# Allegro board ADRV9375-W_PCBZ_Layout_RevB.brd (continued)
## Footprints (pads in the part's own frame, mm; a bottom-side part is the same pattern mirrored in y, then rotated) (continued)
CNSAMTECTSW-108-08-G-D-ST
  rect 1.651x1.651 hole 1.143: 1(0,0)
  round 1.651 hole 1.143: 2(0,2.54) 3(2.54,0) 4(2.54,2.54) 5(5.08,0) 6(5.08,2.54) 7(7.62,0) 8(7.62,2.54) 9(10.16,0) 10(10.16,2.54) 11(12.7,0) 12(12.7,2.54) 13(15.24,0) 14(15.24,2.54) 15(17.78,0) 16(17.78,2.54)
CNWIELAND3225
  rect 2.159x2.159 hole 1.651: 1(0,0)
  round 2.159 hole 1.651: 2(5,0)
DO214AA3
  rect 1.778x2.159 smd: A(2.032,0) C(-2.032,0)
ETC1
  rect 0.762x1.397 smd: 1(-1.27,1.714) 2(0,1.714) 3(1.27,1.714) 4(1.27,-1.714) 5(-1.27,-1.714)
F1206
  rect 1.143x2.032 smd: 1(-1.333,0) 2(1.333,0)
L0201H13
  rect 0.254x0.305 smd: 1(-0.277,0) 2(0.277,0)
L0402
  rect 0.889x0.813 smd: 1(-0.635,0) 2(0.635,0)
L0603
  rect 0.583x0.813 smd: 1(-0.737,0)
  rect 0.889x0.813 smd: 2(0.737,0)
L0805
  rect 1.143x1.27 smd: 1(-0.953,0) 2(0.953,0)
LCC4H210
  rect 1.27x2.286 smd: 1(-2.54,-3.556) 2(2.54,-3.556) 3(2.54,3.556) 4(-2.54,3.556)
LED0603
  rect 0.965x0.762 smd: A(0.8,0) C(-0.8,0)
LED0603_A
  rect 0.889x0.787 smd: A(0.845,0) C(-0.845,0)
LSMSQ157H83
  rect 1.473x3.683 smd: 1(-1.232,0) 2(1.232,0)
LSMSQ157H122
  rect 0.965x3.708 smd: 1(-1.181,0) 2(1.181,0)
MSOP8_PAD2_16X1_73
  rect 0.33x1.575 smd: 1(-0.975,-2.171) 2(-0.325,-2.171) 3(0.325,-2.171) 4(0.975,-2.171) 5(0.975,2.171) 6(0.325,2.171) 7(-0.325,2.171) 8(-0.975,2.171)
  rect 2.159x1.727 smd: PAD(0,0)
POWERPAKSC70-6
  rect 0.305x0.33 smd: 1(-0.65,-0.91) 2(0,-0.91) 3(0.65,-0.91) 4(0.65,0.91) 5(0,0.91) 6(-0.65,0.91)
  rect 0.61x0.94 smd: PAD1(-0.465,0) PAD2(0.465,0)
QFN20_4X4_PAD2_6X2_6
  oval 0.305x1.041 smd: 1(-1,-2.019) 2(-0.5,-2.019) 3(0,-2.019) 4(0.5,-2.019) 5(1,-2.019) 11(1,2.019) 12(0.5,2.019) 13(0,2.019) 14(-0.5,2.019) 15(-1,2.019)
  oval 1.041x0.305 smd: 6(2.019,-1) 7(2.019,-0.5) 8(2.019,0) 9(2.019,0.5) 10(2.019,1) 16(-2.019,1) 17(-2.019,0.5) 18(-2.019,0) 19(-2.019,-0.5) 20(-2.019,-1)
  rect 2.591x2.591 smd: PAD(0,0)
QFN48_7X7_PAD5_6X5_6
  oval 0.305x0.94 smd: 1(-2.75,-3.5) 2(-2.25,-3.5) 3(-1.75,-3.5) 4(-1.25,-3.5) 5(-0.75,-3.5) 6(-0.25,-3.5) 7(0.25,-3.5) 8(0.75,-3.5) 9(1.25,-3.5) 10(1.75,-3.5) 11(2.25,-3.5) 12(2.75,-3.5) 25(2.75,3.5) 26(2.25,3.5) 27(1.75,3.5) 28(1.25,3.5) 29(0.75,3.5) 30(0.25,3.5) 31(-0.25,3.5) 32(-0.75,3.5) 33(-1.25,3.5) 34(-1.75,3.5) 35(-2.25,3.5) 36(-2.75,3.5)
  oval 0.94x0.305 smd: 13(3.5,-2.75) 14(3.5,-2.25) 15(3.5,-1.75) 16(3.5,-1.25) 17(3.5,-0.75) 18(3.5,-0.25) 19(3.5,0.25) 20(3.5,0.75) 21(3.5,1.25) 22(3.5,1.75) 23(3.5,2.25) 24(3.5,2.75) 37(-3.5,2.75) 38(-3.5,2.25) 39(-3.5,1.75) 40(-3.5,1.25) 41(-3.5,0.75) 42(-3.5,0.25) 43(-3.5,-0.25) 44(-3.5,-0.75) 45(-3.5,-1.25) 46(-3.5,-1.75) 47(-3.5,-2.25) 48(-3.5,-2.75)
  rect 5.588x5.588 smd: PAD(0,0)
QFN72_10X10_PAD5_3X5_3
  oval 0.305x0.838 smd: 1(-4.25,-4.95) 2(-3.75,-4.95) 3(-3.25,-4.95) 4(-2.75,-4.95) 5(-2.25,-4.95) 6(-1.75,-4.95) 7(-1.25,-4.95) 8(-0.75,-4.95) 9(-0.25,-4.95) 10(0.25,-4.95) 11(0.75,-4.95) 12(1.25,-4.95) 13(1.75,-4.95) 14(2.25,-4.95) 15(2.75,-4.95) 16(3.25,-4.95) 17(3.75,-4.95) 18(4.25,-4.95) 37(4.25,4.95) 38(3.75,4.95) 39(3.25,4.95) 40(2.75,4.95) 41(2.25,4.95) 42(1.75,4.95) 43(1.25,4.95) 44(0.75,4.95) 45(0.25,4.95) 46(-0.25,4.95) 47(-0.75,4.95) 48(-1.25,4.95) 49(-1.75,4.95) 50(-2.25,4.95) 51(-2.75,4.95) 52(-3.25,4.95) 53(-3.75,4.95) 54(-4.25,4.95)
  oval 0.838x0.305 smd: 19(4.95,-4.25) 20(4.95,-3.75) 21(4.95,-3.25) 22(4.95,-2.75) 23(4.95,-2.25) 24(4.95,-1.75) 25(4.95,-1.25) 26(4.95,-0.75) 27(4.95,-0.25) 28(4.95,0.25) 29(4.95,0.75) 30(4.95,1.25) 31(4.95,1.75) 32(4.95,2.25) 33(4.95,2.75) 34(4.95,3.25) 35(4.95,3.75) 36(4.95,4.25) 55(-4.95,4.25) 56(-4.95,3.75) 57(-4.95,3.25) 58(-4.95,2.75) 59(-4.95,2.25) 60(-4.95,1.75) 61(-4.95,1.25) 62(-4.95,0.75) 63(-4.95,0.25) 64(-4.95,-0.25) 65(-4.95,-0.75) 66(-4.95,-1.25) 67(-4.95,-1.75) 68(-4.95,-2.25) 69(-4.95,-2.75) 70(-4.95,-3.25) 71(-4.95,-3.75) 72(-4.95,-4.25)
  rect 5.994x5.994 smd: PAD(0,0)
R0201
  rect 0.305x0.406 smd: 1(-0.318,0) 2(0.318,0)
R0402
  rect 0.889x0.813 smd: 1(-0.635,0) 2(0.635,0)
R0402#2
  rect 0.61x0.61 smd: 1(-0.495,0) 2(0.495,0)
R0603
  rect 1.092x1.194 smd: 1(-0.851,0) 2(0.851,0)
SC70
  rect 0.406x0.508 smd: 1(-0.65,-0.95) 2(0,-0.95) 3(0.65,-0.95) 4(0.65,0.95) 5(0,0.95) 6(-0.65,0.95)
SC70-6
  rect 0.406x0.508 smd: 1(-0.65,-0.95) 2(0,-0.95) 3(0.65,-0.95) 4(0.65,0.95) 5(0,0.95) 6(-0.65,0.95)
T0805_A
  rect 0.305x0.787 smd: 1(-0.65,-0.644) 2(0,-0.644) 3(0.65,-0.644) 4(0.65,0.644) 5(0,0.644) 6(-0.65,0.644)
TSML150W160H160
  rect 0.762x1.651 smd: 1(-1.27,1.587) 2(0,1.587) 3(1.27,1.587) 4(1.27,-1.587) 5(0,-1.587) 6(-1.27,-1.587)
TSSOP8
  rect 0.33x1.651 smd: 1(-0.975,-2.92) 2(-0.325,-2.92) 3(0.325,-2.92) 4(0.975,-2.92) 5(0.975,2.92) 6(0.325,2.92) 7(-0.325,2.92) 8(-0.975,2.92)
TSSOP14
  rect 0.432x1.778 smd: 1(-1.95,-2.92) 2(-1.3,-2.92) 3(-0.65,-2.92) 4(0,-2.92) 5(0.65,-2.92) 6(1.3,-2.92) 7(1.95,-2.92) 8(1.95,2.92) 9(1.3,2.92) 10(0.65,2.92) 11(0,2.92) 12(-0.65,2.92) 13(-1.3,2.92) 14(-1.95,2.92)
unnamed#2
  round 3.81 hole 2.54 unplated: (0,0)
US8
  rect 0.305x0.711 smd: 1(-0.75,-1.343) 2(-0.25,-1.343) 3(0.25,-1.343) 4(0.75,-1.343) 5(0.75,1.343) 6(0.25,1.343) 7(-0.25,1.343) 8(-0.75,1.343)
YSML276W197H71
  rect 1.803x2.007 smd: 1(-2.54,-2) 2(0,-2) 3(2.54,-2) 4(2.54,2) 5(0,2) 6(-2.54,2)
YSML555W358H240
  rect 1.27x2.54 smd: 1(-2.54,-4.064) 2(0,-4.064) 3(2.54,-4.064) 4(2.54,4.064) 5(0,4.064) 6(-2.54,4.064)

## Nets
AGND: C200.2(N2) C202.2(N2) C203.1(N1) C208.2(N2) C211.2(N2) C212.2(N2) C217.2(N2) C219.2(N2) C220.2(N2) C225.2(N2) C227.2(N2) C228.2(N2) C233.2(N2) C235.2(N2) C236.2(N2) C246.1(N1) C247.1(N1) C248.1(N1) C249.1(N1) C250.1(N1) C307.2(N2) C308.2(N2) C312.1(N1) C313.1(N1) C314.1(N1) C315.2(N2) C316.2(N2) C320.2(N2) C321.1(N1) C322.1(N1) C323.2(N2) C324.2(N2) C325.2(N2) C326.1(N1) C328.2(N2) C329.2(N2) C330.2(N2) C331.2(N2) C334.2(N2) C335.2(N2) C338.1(N1) C339.1(N1) C404.2(N2) C405.1(N1) C406.1(N1) C410.1(N1) C411.1(N1) C413.2(N2) C414.1(N1) C415.1(N1) C416.1(N1) C417.1(N1) C418.1(N1) C419.1(N1) C420.2(N2) C421.1(N1) C422.1(N1) C423.1(N1) C424.1(N1) C425.1(N1) C426.1(N1) C427.1(N1) C428.1(N1) C429.1(N1) C430.1(N1) C431.1(N1) C432.1(N1) C433.1(N1) C434.1(N1) C435.1(N1) C436.1(N1) C437.1(N1) C438.1(N1) C439.1(N1) C503.2(N2) C504.2(N2) C505.2(N2) C506.2(N2) C523.2(N2) C524.2(N2) C525.2(N2) C526.2(N2) C527.2(N2) C528.2(N2) C529.2(N2) C530.2(N2) C531.2(N2) C532.2(N2) C601.2(N2) C602.2(N2) C603.2(N2) C604.2(N2) C605.2(N2) C606.2(N2) C608.2(N2) C609.2(N2) C610.2(N2) C611.2(N2) C612.2(N2) C613.2(N2) C614.2(N2) C615.2(N2) C616.2(N2) C617.2(N2) C618.2(N2) C619.2(N2) C620.2(N2) C621.2(N2) C622.2(N2) C623.2(N2) C624.2(N2) C625.2(N2) C626.2(N2) C627.2(N2) C628.2(N2) C629.2(N2) C630.2(N2) C631.2(N2) C632.2(N2) C633.2(N2) C634.2(N2) C635.2(N2) C636.2(N2) C637.2(N2) C638.2(N2) C639.2(N2) C640.2(N2) C641.2(N2) C642.2(N2) C643.2(N2) C644.2(N2) C645.2(N2) C646.2(N2) C647.2(N2) C648.2(N2) C649.2(N2) C650.2(N2) C651.2(N2) C652.2(N2) C653.2(N2) C654.2(N2) C701.2(N2) C702.1(N1) C703.1(N1) C704.1(N1) C705.2(N2) C706.1(N1) C707.2(N2) C708.1(N1) C709.2(N2) C710.1(N1) C711.1(N1) C712.1(N1) C721.2(N2) C722.2(N2) C723.2(N2) C725.2(N2) C726.2(N2) C728.2(N2) C730.2(N2) C732.2(N2) C733.1(N1) C734.1(N1) C735.1(N1) C736.2(N2) C737.1(N1) C738.1(N1) C739.2(N2) C803.1(N1) C804.2(N2) D401.C(N) D402.C(N) DS702.C(N) J200.2(SH1) J200.3(SH2) J200.4(SH3) J200.5(SH4) J201.2(SH1) J201.3(SH2) J201.4(SH3) J201.5(SH4) J202.2(SH1) J202.3(SH2) J202.4(SH3) J202.5(SH4) J203.2(SH1) J203.3(SH2) J203.4(SH3) J203.5(SH4) J204.2(SH1) J204.3(SH2) J204.4(SH3) J204.5(SH4) J305.2(SH1) J305.3(SH2) J305.4(SH3) J305.5(SH4) J306.2(SH1) J306.3(SH2) J306.4(SH3) J306.5(SH4) J307.2(SH1) J307.3(SH2) J307.4(SH3) J307.5(SH4) J308.2(SH1) J308.3(SH2) J308.4(SH3) J308.5(SH4) J401.2(SH1) J401.3(SH2) J401.4(SH3) J401.5(SH4) P501.1(N1) P501.2(N2) P502.1(N1) P503.1(N1) P503.3(N2) P503.14(N7) P503.16(N8) P504.3(N2) P504.5(N3) P504.9(N5) P504.15(N8) P504.19(N10) P701.2(N2) P703.2(N2) P704.2(N2) P705.2(N2) P706.2(N2) P707.2(N2) P801.A1(N1) P801.A4(N4) P801.A5(N5) P801.A8(N8) P801.A9(N9) P801.A12(N12) P801.A13(N13) P801.A16(N16) P801.A17(N17) P801.A20(N20) P801.A21(N21) P801.A24(N24) P801.A25(N25) P801.A28(N28) P801.A29(N29) P801.A32(N32) P801.A33(N33) P801.A36(N36) P801.A37(N37) P801.A40(N40) P801.B2(N2) P801.B3(N3) P801.B6(N6) P801.B7(N7) P801.B10(N10) P801.B11(N11) P801.B14(N14) P801.B15(N15) P801.B18(N18) P801.B19(N19) P801.B22(N22) P801.B23(N23) P801.B26(N26) P801.B27(N27) P801.B30(N30) P801.B31(N31) P801.B34(N34) P801.B35(N35) P801.B38(N38) P801.B39(N39) P801.C1(N1) P801.C4(N4) P801.C5(N5) P801.C8(N8) P801.C9(N9) P801.C12(N12) P801.C13(N13) P801.C16(N16) P801.C17(N17) P801.C20(N20) P801.C21(N21) P801.C24(N24) P801.C25(N25) P801.C28(N28) P801.C29(N29) P801.C32(N32) P801.C33(N33) P801.C36(N36) P801.C38(N38) P801.C40(N40) P801.D2(N2) P801.D3(N3) P801.D6(N6) P801.D7(N7) P801.D10(N10) P801.D13(N13) P801.D16(N16) P801.D19(N19) P801.D22(N22) P801.D25(N25) P801.D28(N28) P801.D37(N37) P801.D39(N39) P801.E1(N1) P801.E4(N4) P801.E5(N5) P801.E8(N8) P801.E11(N11) P801.E14(N14) P801.E17(N17) P801.E20(N20) P801.E23(N23) P801.E26(N26) P801.E29(N29) P801.E32(N32) P801.E35(N35) P801.E38(N38) P801.E40(N40) P801.F2(N2) P801.F3(N3) P801.F6(N6) P801.F9(N9) P801.F12(N12) P801.F15(N15) P801.F18(N18) P801.F21(N21) P801.F24(N24) P801.F27(N27) P801.F30(N30) P801.F33(N33) P801.F36(N36) P801.F39(N39) P801.G1(N1) P801.G4(N4) P801.G5(N5) P801.G8(N8) P801.G11(N11) P801.G14(N14) P801.G17(N17) P801.G20(N20) P801.G23(N23) P801.G26(N26) P801.G29(N29) P801.G32(N32) P801.G35(N35) P801.G38(N38) P801.G40(N40) P801.H3(N3) P801.H6(N6) P801.H9(N9) P801.H12(N12) P801.H15(N15) P801.H18(N18) P801.H21(N21) P801.H24(N24) P801.H27(N27) P801.H30(N30) P801.H33(N33) P801.H36(N36) P801.H39(N39) P801.J1(N1) P801.J4(N4) P801.J5(N5) P801.J8(N8) P801.J11(N11) P801.J14(N14) P801.J17(N17) P801.J20(N20) P801.J23(N23) P801.J26(N26) P801.J29(N29) P801.J32(N32) P801.J35(N35) P801.J38(N38) P801.J40(N40) P801.K2(N2) P801.K3(N3) P801.K6(N6) P801.K9(N9) P801.K12(N12) P801.K15(N15) P801.K18(N18) P801.K21(N21) P801.K24(N24) P801.K27(N27) P801.K30(N30) P801.K33(N33) P801.K36(N36) P801.K39(N39) Q701.1(S1) Q701.4(S2) R401.1(N1) R402.1(N1) R403.1(N1) R404.2(N2) R409.1(N1) R417.1(N1) R418.2(N2) R419.2(N2) R428.2(N2) R504.2(N2) R505.1(N1) R506.2(N2) R507.2(N2) R508.2(N2) R509.2(N2) R514.2(N2) R515.2(N2) R516.2(N2) R517.2(N2) R518.2(N2) R525.1(N1) R603.2(N2) R605.1(N1) R607.1(N1) R609.1(N1) R611.1(N1) R613.1(N1) R701.1(N1) R706.2(N2) R710.2(N2) R713.2(N2) R714.2(N2) R718.1(N1) R719.1(N1) R720.1(N1) R724.1(N1) R728.1(N1) R732.2(N2) R733.2(N2) R734.2(N2) R737.2(N2) R740.1(N1) R801.1(N1) R819.1(N1) R821.1(N1) R823.1(N1) T200.1(NC1) T201.1(NC1) T202.1(NC1) T203.1(NC1) T204.1(NC1) T305.1(NC1) T306.1(NC1) T307.2(GND1) T307.5(GND2) T308.2(GND1) T308.5(GND2) U101.A1(VSSA_1) U101.A4(VSSA_2) U101.A7(VSSA_3) U101.A8(VSSA_4) U101.A11(VSSA_5) U101.A14(VSSA_6) U101.B2(VSSA_7) U101.B3(VSSA_8) U101.B4(VSSA_9) U101.B5(VSSA_10) U101.B6(VSSA_11) U101.B9(VSSA_12) U101.B10(VSSA_13) U101.B11(VSSA_14) U101.B12(VSSA_15) U101.B13(VSSA_16) U101.C5(VSSA_17) U101.C9(VSSA_18) U101.C10(VSSA_19) U101.D2(SNRXC-) U101.D3(SNRXB-) U101.D6(VSSA_20) U101.D7(VSSA_21) U101.D8(VSSA_22) U101.D9(VSSA_23) U101.E2(SNRXC+) U101.E3(SNRXB+) U101.E6(VSSA_24) U101.E9(VSSA_25) U101.E10(VSSA_71) U101.F3(VSSA_26) U101.F4(VSSA_27) U101.F5(VSSA_28) U101.F6(VSSA_29) U101.F7(VSSA_30) U101.F8(VSSA_31) U101.F9(VSSA_32) U101.F10(VSSA_33) U101.G1(VSSA_34) U101.G2(VSSA_35) U101.G3(VSSA_36) U101.G5(VSSA_37) U101.G10(VSSA_38) U101.G11(VSSA_39) U101.G12(VSSA_40) U101.G13(VSSA_41) U101.G14(VSSA_42) U101.H2(VSSA_43) U101.H3(VSSA_44) U101.H4(VSSA_45) U101.H5(VSSA_46) U101.H6(VSSA_47) U101.H7(VSSA_48) U101.H8(VSSA_49) U101.H9(VSSA_50) U101.H10(VSSA_51) U101.H13(VSSA_52) U101.J2(VSSA_53) U101.J13(VSSA_54) U101.K1(VSSA_55) U101.K2(VSSA_56) U101.K13(VSSA_57) U101.K14(VSSA_58) U101.L1(VSSA_59) U101.L2(VSSA_60) U101.L7(VSSD_1) U101.L10(VSSD_2) U101.L13(VSSA_61) U101.L14(VSSA_62) U101.M2(VSSA_63) U101.M9(VSSA_64) U101.N2(VSSA_65) U101.N7(VSSA_66) U101.N14(VSSA_67) U101.P1(VSSA_72) U101.P2(VSSA_68) U101.P3(VSSA_69) U101.P10(VSSA_70) U401.4(REF_SEL) U401.9(NIC1) U401.13(NIC2) U401.PAD U402.2(GND) U403.4(GND) U404.3(GND) U405.7(GND) U601.6(GND1) U601.9(GND) U601.PAD U701.2(PGND3_1) U701.3(PGND3_2) U701.10(PGND4_1) U701.11(PGND4_2) U701.30(PGND) U701.PAD(EP) U702.4(GND) U702.PAD(EP) U801.4(VSS) U801.7(WC_N) Y401.3(GND) Y402.3(GND) Y403.2(GND)
VDD_IF: C415.2(N2) C417.2(N2) C419.2(N2) C642.1(N1) C643.1(N1) C734.2(N2) C735.2(N2) P504.1(N1) P707.1(N1) P801.J39(N39) P801.K40(N40) R502.1(N1) R503.1(N1) R510.1(N1) R511.1(N1) R512.1(N1) R513.1(N1) R606.1(N1) R738.2(N2) R739.2(N2) R808.1(N1) R809.1(N1) U101.M12(VDD_IF) U403.8(VCC) U404.1(VCCA) U404.4(EN) U405.1(VCCA) U405.8(EN) U702.1(VOUT1) U702.2(VOUT2)
VDD_IF_LDO: C733.2(N2) R736.2(N2) U702.5(EN) U702.7(VIN1) U702.8(VIN2)
VDDA_CALPLL: C614.1(N1) C615.1(N1) E602.2(N2) U101.G4(VDDA_CALPLL)
VDDA_CLK: C616.1(N1) C617.1(N1) E603.2(N2) U101.N1(VDDA_CLK)
VDDA_CLKSYNTH: C618.1(N1) C619.1(N1) E604.2(N2) U101.G6(VDDA_CLKSYNTH)
VDDA_DES: C652.1(N1) C653.1(N1) C654.1(N1) E613.2(N2) U101.N9(VDDA_DES) U101.P9(JESD_VTT_DES)
VDDA_RXLO: C620.1(N1) C621.1(N1) E605.2(N2) U101.C6(VDDA_RXLO)
VDDA_RXSYNTH: C622.1(N1) C623.1(N1) E606.2(N2) U101.G9(VDDA_RXSYNTH)
VDDA_RXTX: C608.1(N1) C609.1(N1) C610.1(N1) R601.2(N2) U101.F2(VDDA_RXTX)
VDDA_RXVCO: C624.1(N1) C625.1(N1) E607.2(N2) U101.C7(VDDA_RXVCO)
VDDA_SER: C611.1(N1) C612.1(N1) C613.1(N1) E601.2(N2) U101.N8(VDDA_SER) U101.P8(VDDA_SER1)
VDDA_SNRXSYNTH: C626.1(N1) C627.1(N1) E608.2(N2) U101.G7(VDDA_SNRXSYNTH)
VDDA_SNRXVCO: C628.1(N1) C629.1(N1) E609.2(N2) U101.C4(VDDA_SNRXVCO)
VDDA_TXLO: C634.1(N1) C635.1(N1) E612.2(N2) U101.F12(VDDA_TXLO)
VDDA_TXSYNTH: C632.1(N1) C633.1(N1) E611.2(N2) U101.G8(VDDA_TXSYNTH)
VDDA_TXVCO: C630.1(N1) C631.1(N1) E610.2(N2) U101.F11(VDDA_TXVCO)
1P3_BUCK_OUT: C716.2(N2) C725.1(N1) C726.1(N1) E702.1(N1) L701.2(N2) R705.1(N1) R722.2(N2)
3P3V_CLK: C414.2(N2) C416.2(N2) C418.2(N2) C420.1(N1) C421.2(N2) C422.2(N2) C423.2(N2) C424.2(N2) C425.2(N2) C426.2(N2) C427.2(N2) C428.2(N2) C429.2(N2) C430.2(N2) C431.2(N2) C432.2(N2) C433.2(N2) C434.2(N2) C435.2(N2) C436.2(N2) C437.2(N2) C438.2(N2) C439.2(N2) E705.2(N2) R416.1(N1) U401.1(VDD_1) U401.10(VDD_2) U401.16(VDD_3) U401.20(VDD_4) U401.27(VDD13) U401.30(VDD12) U401.33(VDD11) U401.36(VDD10) U401.39(VDD9) U401.42(VDD8) U401.45(VDD7) U401.48(VDD6) U401.51(VDD5) U401.54(VDD4) U401.60(VDD3) U401.63(VDD2) U401.66(VDD1) U401.69(VDD0) U401.72(VDD_5) U402.5(VCC) U404.6(VCCY) U405.14(VCCY)
3P3V_VCO: C405.2(N2) C738.2(N2) E706.2(N2) R408.2(N2) Y401.6(VDD) Y402.6(POS_VS) Y403.4(VDD)
3P3VAUX: C648.1(N1) C649.1(N1) C803.2(N2) C804.1(N1) P801.D32(N32) R818.2(N2) R820.2(N2) R822.2(N2) U601.10(VDD) U601.16(VDRIVE) U601.17(PD_N/RST_N) U801.8(VCC)
ADP5054_EN: P801.D1(N1) R702.1(N1)
ADP5054_VREG: C702.2(N2) R703.2(N2) U701.13(CFG34) U701.18(CFG12) U701.44(SYNC/MODE) U701.45(VREG)
AUXADC_0: C506.1(N1) P501.3(N3) U101.E13(AUXADC_0)
AUXADC_1: C505.1(N1) P501.4(N4) U101.C11(AUXADC_1)
AUXADC_2: C504.1(N1) P501.5(N5) U101.C12(AUXADC_2)
AUXADC_3: C503.1(N1) P501.6(N6) U101.D11(AUXADC_3)
BAL_TX1+: C303.1(N1) L309.1(N1) T305.5(SEC_DOT)
BAL_TX1-: C303.2(N2) L310.1(N1) T305.4(SEC)
BAL_TX2+: C304.1(N1) L317.1(N1) T306.5(SEC_DOT)
BAL_TX2-: C304.2(N2) L318.1(N1) T306.4(SEC)
BAL_TX_OUT1: C305.1(N1) T305.3(PRI_DOT)
BAL_TX_OUT2: C306.1(N1) T306.3(PRI_DOT)
CLK+: C402.2(N2) R406.1(N1) U401.2(REFA)
CLK-: C403.2(N2) R406.2(N2) U401.3(REFA_N)
CLK_RESETB: R416.2(N2) U401.19(RESET_N) U404.5(Y)
CLK_SYSREF_REQUEST: R417.2(N2) U401.57(SYSREF_REQ) U405.13(Y1)
COMP_OUT: R411.1(N1) Y401.5(COMP_OUT) Y402.5(NC)
DEV_CLK_IN+: C502.1(N1) R425.1(N1) R501.2(N2) U401.25(OUT13)
DEV_CLK_IN-: C501.1(N1) R425.2(N2) R501.1(N1) U401.26(OUT13_N)
DIR_CLK+: C402.1(N1) C409.1(N1) R403.2(N2) R405.1(N1) T401.1(N1)
DIR_CLK-: C403.1(N1) C407.1(N1) R404.1(N1) R405.2(N2) T401.3(N2)
EPROM_A0: P801.C34(N34) R818.1(N1) R819.2(N2) U601.11(AS0) U801.1(E0)
EPROM_A1: P801.D35(N35) R820.1(N1) R821.2(N2) U601.13(AS1) U801.2(E1)
FMC_CLK_RESETB: P801.D26(N26) U404.2(A)
FMC_SYSREF_REQUEST: P801.D27(N27) U405.2(A1)
FMCA_SCL: P801.C30(N30) U601.15(SCL) U801.6(SCL)
FMCA_SDA: P801.C31(N31) U601.14(SDA) U801.5(SDA)
FMCA_VADJ: C732.1(N1) P801.E39(N39) P801.F40(N40) P801.G39(N39) P801.H40(N40) R738.1(N1) TP812.1(N1)
FMCA_VCC_3P3V: P801.C39(N39) P801.D36(N36) P801.D38(N38) P801.D40(N40) TP816.1(N1)
FMCA_VCC_12P0V: F701.1(N1) P801.C35(N35) P801.C37(N37) TP815.1(N1)
FPGA_AUX_CLK+: C805.1(N1) R429.1(N1) U401.61(OUT2)
FPGA_AUX_CLK-: C806.1(N1) R429.2(N2) U401.62(OUT2_N)
FPGA_REF_CLK+: C801.2(N2) R422.1(N1) U401.64(OUT1)
FPGA_REF_CLK-: C802.2(N2) R422.2(N2) U401.65(OUT1_N)
FPGA_SYSREF+: P801.G36(N36) R423.2(N2) U401.58(OUT3)
FPGA_SYSREF-: P801.G37(N37) R423.1(N1) U401.59(OUT3_N)
GP_INTERRUPT: R803.1(N1) TP803.1(N1) U101.J5(GP_INTERRUPT)
GPIO_0: P502.2(N2) P801.H19(N19) R513.2(N2) R517.1(N1) U101.K8(GPIO_0)
GPIO_1: P502.3(N3) P801.H20(N20) R512.2(N2) R516.1(N1) U101.J8(GPIO_1)
GPIO_2: P502.4(N4) P801.G18(N18) R511.2(N2) R515.1(N1) U101.J7(GPIO_2)
GPIO_3: P502.5(N5) P801.G19(N19) R510.2(N2) R514.1(N1) U101.K7(GPIO_3)
GPIO_3P3_0: C523.1(N1) P503.5(N3) U101.C1(GPIO_3P3_0)
GPIO_3P3_1: C524.1(N1) P503.7(N4) U101.C2(GPIO_3P3_1)
GPIO_3P3_2: P503.9(N5) U101.F1(GPIO_3P3_2)
GPIO_3P3_3: C525.1(N1) P503.11(N6) U101.D1(GPIO_3P3_3)
GPIO_3P3_4: C526.1(N1) P503.13(N7) U101.E1(GPIO_3P3_4)
GPIO_3P3_5: C527.1(N1) P503.15(N8) U101.D5(GPIO_3P3_5)
GPIO_3P3_6: C528.1(N1) P503.2(N1) U101.E14(GPIO_3P3_6)
GPIO_3P3_7: C529.1(N1) P503.4(N2) U101.D12(GPIO_3P3_7)
GPIO_3P3_8: C530.1(N1) P503.6(N3) U101.D13(GPIO_3P3_8)
GPIO_3P3_9: C531.1(N1) P503.8(N4) U101.C13(GPIO_3P3_9)
GPIO_3P3_10: C532.1(N1) P503.10(N5) U101.D14(GPIO_3P3_10)
GPIO_3P3_11: P503.12(N6) U101.F14(GPIO_3P3_11)
GPIO_4: P502.6(N6) P801.H25(N25) R524.1(N1) U101.K6(GPIO_4)
GPIO_5: P502.7(N7) P801.H26(N26) R522.1(N1) U101.K5(GPIO_5)
GPIO_6: P502.8(N8) P801.C22(N22) R523.1(N1) U101.L5(GPIO_6)
GPIO_7: P502.9(N9) P801.C23(N23) R519.1(N1) U101.L6(GPIO_7)
GPIO_8: P502.10(N10) P801.G25(N25) R520.1(N1) U101.L12(GPIO_8)
GPIO_9: P502.11(N11) P801.H22(N22) U101.K12(GPIO_9)
GPIO_10: P502.12(N12) P801.H23(N23) U101.J12(GPIO_10)
GPIO_11: P502.13(N13) P801.G21(N21) U101.H12(GPIO_11)
GPIO_12: P502.14(N14) P801.G22(N22) U101.H11(GPIO_12)
GPIO_13: P502.15(N15) P801.G31(N31) U101.J11(GPIO_13)
GPIO_14: P502.16(N16) P801.G30(N30) U101.K11(GPIO_14)
GPIO_15: P502.17(N17) P801.G24(N24) U101.L11(GPIO_15)
GPIO_16: P502.18(N18) P801.G16(N16) U101.M11(GPIO_16)
GPIO_17: P502.19(N19) P801.G15(N15) U101.M10(GPIO_17)
GPIO_18: P502.20(N20) P801.D12(N12) R518.1(N1) R521.1(N1) U101.J3(GPIO_18)
INPUT_VOLTAGE: C701.1(N1) C705.1(N1) C707.1(N1) C709.1(N1) CR701.C(N) DS701.A(P) R602.2(N2) R709.1(N1) U701.6(PVIN3) U701.7(PVIN4) U701.22(PVIN2_1) U701.23(PVIN2_2) U701.24(PVIN2_3) U701.36(PVIN1_1) U701.37(PVIN1_2) U701.38(PVIN1_3)
JTAG_TDI: P801.D30(N30) R815.2(N2)
JTAG_TDO: P801.D31(N31) R815.1(N1)
LDO_VCO_2P5: C412.1(N1) C413.1(N1) U401.15(LDO_VCO)
LF_EXT_CAP: C410.2(N2) R415.2(N2) U401.7(LF1)
LF_PLL2: C412.2(N2) U401.14(LF2_CAP)
ORX1+: C232.2(N2) L231.1(N1) U101.A12(ORX1+)
ORX1-: C232.1(N1) L230.1(N1) U101.A13(ORX1-)
ORX2+: C240.2(N2) L239.1(N1) U101.A2(ORX2+)
ORX2-: C240.1(N1) L238.1(N1) U101.A3(ORX2-)
OUT: R410.1(N1) Y401.4(OUT) Y402.4(OUTPUT) Y403.3(OUT)
RESETB: R502.2(N2) R802.1(N1) TP804.1(N1) U101.J4(RESET_N)
RX1+: C207.2(N2) L205.1(N1) U101.A9(RX1+)
RX1-: C207.1(N1) L206.1(N1) U101.A10(RX1-)
RX1_ENABLE: P501.7(N7) R508.1(N1) R814.1(N1) U101.M5(RX1_ENABLE)
RX2+: C216.1(N1) L214.1(N1) U101.A5(RX2+)
RX2-: C216.2(N2) L215.1(N1) U101.A6(RX2-)
RX2_ENABLE: P501.8(N8) R509.1(N1) R817.1(N1) U101.M7(RX2_ENABLE)
RX_EXTLO+: C332.2(N2) U101.B8(RX_EXTLO+)
RX_EXTLO-: C333.2(N2) U101.B7(RX_EXTLO-)
SERDIN0+: C508.1(N1) P801.A26(N26)
SERDIN0-: C507.1(N1) P801.A27(N27)
SERDIN1+: C510.1(N1) P801.C2(N2)
SERDIN1-: C509.1(N1) P801.C3(N3)
SERDIN2+: C512.1(N1) P801.A30(N30)
SERDIN2-: C511.1(N1) P801.A31(N31)
SERDIN3+: C514.1(N1) P801.A22(N22)
SERDIN3-: C513.1(N1) P801.A23(N23)
SERDOUT0+: C516.1(N1) P801.A2(N2)
SERDOUT0-: C515.1(N1) P801.A3(N3)
SERDOUT1+: C518.1(N1) P801.A6(N6)
SERDOUT1-: C517.1(N1) P801.A7(N7)
SERDOUT2+: C520.1(N1) P801.C6(N6)
SERDOUT2-: C519.1(N1) P801.C7(N7)
SERDOUT3+: C522.1(N1) P801.A10(N10)
SERDOUT3-: C521.1(N1) P801.A11(N11)
SNRXA+: C224.1(N1) L222.1(N1) U101.E4(SNRXA+)
SNRXA-: C224.2(N2) L223.1(N1) U101.D4(SNRXA-)
SPI_CLK: R804.1(N1) TP802.1(N1) U101.K9(SCLK) U405.3(A2)
SPI_CLK_9528: U401.22(SCLK/SCL) U405.12(Y2)
SPI_CS0: R808.2(N2) R811.1(N1) TP813.1(N1) U101.K10(CSB) U403.7(OE2_N)
SPI_CS1: R809.2(N2) R812.1(N1) TP814.1(N1) U403.1(OE1_N) U405.5(A4)
SPI_CS_9528: U401.21(CS_N) U405.10(Y4)
SPI_DIN: R805.1(N1) TP801.1(N1) U101.J9(SDIO) U405.4(A3)
SPI_DIN_9528: U401.23(SDIO/SDA) U405.11(Y3)
SPI_DOUT: R806.1(N1) TP809.1(N1) U403.3(Y2) U403.6(Y1)
SPI_DOUT_9370: R427.2(N2) TP402.1(N1) U101.J10(SDO)
SPI_DOUT_9528: R426.2(N2) TP401.1(N1) U401.24(SDO)
STATUS_0: R418.1(N1) U401.55(STATUS0/SP0) U402.1(A1)
STATUS_1: R419.1(N1) U401.56(STATUS1/SP1) U402.3(A2)
SYNCINB0+: P801.G9(N9) TP807.1(N1) U101.M4(SYNCINB0+)
SYNCINB0-: P801.G10(N10) TP808.1(N1) U101.M3(SYNCINB0-)
SYNCINB1+: P801.G27(N27) TP810.1(N1) U101.L4(SYNCINB1+)
SYNCINB1-: P801.G28(N28) TP811.1(N1) U101.L3(SYNCINB1-)
SYNCOUTB0+: P801.H7(N7) TP805.1(N1) U101.M13(SYNCOUTB0+)
SYNCOUTB0-: P801.H8(N8) TP806.1(N1) U101.M14(SYNCOUTB0-)
SYSREF_IN+: R424.2(N2) U101.K3(SYSREF_IN+) U401.28(OUT12)
SYSREF_IN-: R424.1(N1) U101.K4(SYSREF_IN-) U401.29(OUT12_N)
TEST: R503.2(N2) R504.1(N1) R810.1(N1) U101.J6(TEST)
TRI_STATE: R408.1(N1) R409.2(N2) Y401.2(TRI_STATE) Y402.2(ENABLE_DISABLE)
TX1+: C311.1(N1) L307.1(N1) L309.2(N2) U101.H14(TX1+)
TX1-: C311.2(N2) L308.2(N2) L310.2(N2) U101.J14(TX1-)
TX1_ENABLE: P501.9(N9) R507.1(N1) R813.1(N1) U101.M6(TX1_ENABLE)
TX2+: C319.1(N1) L315.1(N1) L317.2(N2) U101.J1(TX2+)
TX2-: C319.2(N2) L316.2(N2) L318.2(N2) U101.H1(TX2-)
TX2_ENABLE: P501.10(N10) R506.1(N1) R816.1(N1) U101.M8(TX2_ENABLE)
TX_EXTLO+: C336.2(N2) U101.E12(TX_EXTLO+)
TX_EXTLO-: C337.2(N2) U101.E11(TX_EXTLO-)
UNNAMED_3_CAP_I11_N1: C200.1(N1) J200.1(CNTR) R201.1(N1)
UNNAMED_3_CAP_I25_N1: C208.1(N1) J201.1(CNTR) R209.1(N1)
UNNAMED_3_CAP_I39_N1: C217.1(N1) J202.1(CNTR) L218.2(N2)
UNNAMED_3_CAP_I54_N1: C225.1(N1) J203.1(CNTR) L226.2(N2)
UNNAMED_3_CAP_I67_N1: C233.1(N1) J204.1(CNTR) L234.2(N2)
UNNAMED_3_CAP_I109_N1: C213.1(N1) L214.2(N2) T201.5(SEC_DOT)
UNNAMED_3_CAP_I109_N2: C213.2(N2) L215.2(N2) T201.4(SEC)
UNNAMED_3_CAP_I141_N1: C229.1(N1) L230.2(N2) T203.5(SEC_DOT)
UNNAMED_3_CAP_I141_N2: C229.2(N2) L231.2(N2) T203.4(SEC)
UNNAMED_3_CAP_I188_N1: C237.1(N1) L238.2(N2) T204.5(SEC_DOT)
UNNAMED_3_CAP_I188_N2: C237.2(N2) L239.2(N2) T204.4(SEC)
UNNAMED_3_CAP_I194_N1: C211.1(N1) C241.1(N1) R209.2(N2)
UNNAMED_3_CAP_I194_N2: C241.2(N2) T201.3(PRI_DOT)
UNNAMED_3_CAP_I197_N1: C219.1(N1) C242.1(N1) L218.1(N1)
UNNAMED_3_CAP_I197_N2: C242.2(N2) T202.3(PRI_DOT)
UNNAMED_3_CAP_I199_N1: C227.1(N1) C243.1(N1) L226.1(N1)
UNNAMED_3_CAP_I199_N2: C243.2(N2) T203.3(PRI_DOT)
UNNAMED_3_CAP_I201_N1: C235.1(N1) C244.1(N1) L234.1(N1)
UNNAMED_3_CAP_I201_N2: C244.2(N2) T204.3(PRI_DOT)
UNNAMED_3_CAP_I204_N1: C212.1(N1) C247.2(N2) T201.2(PRI/GND)
UNNAMED_3_CAP_I208_N1: C220.1(N1) C250.2(N2) T202.2(PRI/GND)
UNNAMED_3_CAP_I212_N1: C236.1(N1) C249.2(N2) T204.2(PRI/GND)
UNNAMED_3_CAP_I216_N1: C228.1(N1) C248.2(N2) T203.2(PRI/GND)
UNNAMED_3_CAP_I223_N1: C202.1(N1) C245.1(N1) R201.2(N2)
UNNAMED_3_CAP_I223_N2: C245.2(N2) T200.3(PRI_DOT)
UNNAMED_3_CAP_I224_N2: C203.2(N2) C246.2(N2) T200.2(PRI/GND)
UNNAMED_3_CAP_I234_N1: C204.1(N1) L205.2(N2) T200.5(SEC_DOT)
UNNAMED_3_CAP_I234_N2: C204.2(N2) L206.2(N2) T200.4(SEC)
UNNAMED_3_IND_I132_N2: L221.1(N1) L222.2(N2) T202.4(SEC)
UNNAMED_3_IND_I134_N2: L221.2(N2) L223.2(N2) T202.5(SEC_DOT)
UNNAMED_4_CAP_I388_N1: C333.1(N1) T307.4(BAL2)
UNNAMED_4_CAP_I389_N1: C332.1(N1) T307.3(BAL1)
UNNAMED_4_CAP_I525_N1: C305.2(N2) C323.1(N1) L301.2(N2)
UNNAMED_4_CAP_I526_N1: C324.1(N1) J305.1(CNTR) L301.1(N1)
UNNAMED_4_CAP_I531_N1: C329.1(N1) J306.1(CNTR) L302.1(N1)
UNNAMED_4_CAP_I533_N1: C306.2(N2) C328.1(N1) L302.2(N2)
UNNAMED_4_CAP_I561_N1: C331.1(N1) R312.2(N2) T307.1(UNBAL)
UNNAMED_4_CAP_I563_N1: C330.1(N1) J307.1(CNTR) R312.1(N1)
UNNAMED_4_CAP_I600_N2: C314.2(N2) C322.2(N2) C326.2(N2) C339.2(N2) T306.2(PRI/GND)
UNNAMED_4_CAP_I601_N1: C335.1(N1) R313.2(N2) T308.1(UNBAL)
UNNAMED_4_CAP_I603_N1: C334.1(N1) J308.1(CNTR) R313.1(N1)
UNNAMED_4_CAP_I646_N2: C312.2(N2) C313.2(N2) C321.2(N2) C338.2(N2) T305.2(PRI/GND)
UNNAMED_4_CAP_I696_N1: C336.1(N1) T308.3(BAL1)
UNNAMED_4_CAP_I697_N1: C337.1(N1) T308.4(BAL2)
UNNAMED_5_CAP_I803_N2: C411.2(N2) R415.1(N1)
UNNAMED_5_CAP_I900_N2: C406.2(N2) R412.1(N1) R413.2(N2) R428.1(N1)
UNNAMED_5_CAP_I905_N1: C401.1(N1) J401.1(CNTR) R401.2(N2)
UNNAMED_5_CAP_I905_N2: C401.2(N2) T401.4(N3)
UNNAMED_5_CAP_I916_N1: C408.1(N1) R411.2(N2) R413.1(N1)
UNNAMED_5_CMOSNC7WV125K8X_I90_1: R427.1(N1) U403.5(A2)
UNNAMED_5_CMOSNC7WV125K8X_I90_A: R426.1(N1) U403.2(A1)
UNNAMED_5_DIOLED_I865_P: D401.A(P) R420.2(N2)
UNNAMED_5_DIOLED_I866_P: D402.A(P) R421.2(N2)
UNNAMED_5_NC7WZ17P6X_I868_Y1: R421.1(N1) U402.6(Y1)
UNNAMED_5_NC7WZ17P6X_I868_Y2: R420.1(N1) U402.4(Y2)
UNNAMED_5_RES_I897_N2: R410.2(N2) R412.2(N2) R414.1(N1)
UNNAMED_5_RES_I907_N2: R402.2(N2) T401.5(N4)
UNNAMED_6_AD9375_I826_DEVCLKIN: C501.2(N2) U101.E8(DEV_CLK_IN-)
UNNAMED_6_AD9375_I826_DEVCLKIN_: C502.2(N2) U101.E7(DEV_CLK_IN+)
UNNAMED_6_AD9375_I826_RBIAS: R505.2(N2) U101.C14(RBIAS)
UNNAMED_6_AD9375_I832_SERDIN0: C508.2(N2) U101.P12(SERDIN0+)
UNNAMED_6_AD9375_I832_SERDIN0_1: C507.2(N2) U101.P11(SERDIN0-)
UNNAMED_6_AD9375_I832_SERDIN1: C510.2(N2) U101.P14(SERDIN1+)
UNNAMED_6_AD9375_I832_SERDIN1_1: C509.2(N2) U101.P13(SERDIN1-)
UNNAMED_6_AD9375_I832_SERDIN2: C512.2(N2) U101.N11(SERDIN2+)
UNNAMED_6_AD9375_I832_SERDIN2_1: C511.2(N2) U101.N10(SERDIN2-)
UNNAMED_6_AD9375_I832_SERDIN3: C514.2(N2) U101.N13(SERDIN3+)
UNNAMED_6_AD9375_I832_SERDIN3_1: C513.2(N2) U101.N12(SERDIN3-)
UNNAMED_6_AD9375_I832_SERDOUT0: C516.2(N2) U101.P7(SERDOUT0+)
UNNAMED_6_AD9375_I832_SERDOUT0_: C515.2(N2) U101.P6(SERDOUT0-)
UNNAMED_6_AD9375_I832_SERDOUT1: C518.2(N2) U101.P5(SERDOUT1+)
UNNAMED_6_AD9375_I832_SERDOUT1_: C517.2(N2) U101.P4(SERDOUT1-)
UNNAMED_6_AD9375_I832_SERDOUT2: C520.2(N2) U101.N6(SERDOUT2+)
UNNAMED_6_AD9375_I832_SERDOUT2_: C519.2(N2) U101.N5(SERDOUT2-)
UNNAMED_6_AD9375_I832_SERDOUT3: C522.2(N2) U101.N4(SERDOUT3+)
UNNAMED_6_AD9375_I832_SERDOUT3_: C521.2(N2) U101.N3(SERDOUT3-)
UNNAMED_6_CN20PV2_I813_N6: P504.11(N6) TP502.1(N1)
UNNAMED_6_CN20PV2_I813_N7: P504.13(N7) TP501.1(N1)
UNNAMED_6_CN20PV2_I813_N9: P504.17(N9) R525.2(N2)
UNNAMED_6_CN20PV2_I814_N1: P504.2(N1) R519.2(N2)
UNNAMED_6_CN20PV2_I814_N2: P504.4(N2) R520.2(N2) R521.2(N2)
UNNAMED_6_CN20PV2_I814_N3: P504.6(N3) R522.2(N2)
UNNAMED_6_CN20PV2_I814_N4: P504.8(N4) R523.2(N2)
UNNAMED_6_CN20PV2_I814_N8: P504.16(N8) R524.2(N2)
UNNAMED_7_AD7291_I1067_DCAP: C651.1(N1) U601.8(DCAP)
UNNAMED_7_AD7291_I1067_VIN0: R602.1(N1) R603.1(N1) U601.18(VIN0)
UNNAMED_7_AD7291_I1067_VIN1: R604.2(N2) R605.2(N2) U601.19(VIN1)
UNNAMED_7_AD7291_I1067_VIN2: R606.2(N2) R607.2(N2) U601.20(VIN2)
UNNAMED_7_AD7291_I1067_VIN3: R608.2(N2) R609.2(N2) U601.1(VIN3)
UNNAMED_7_AD7291_I1067_VIN5: R610.2(N2) R611.2(N2) U601.3(VIN5)
UNNAMED_7_AD7291_I1067_VIN7: R612.2(N2) R613.2(N2) U601.5(VIN7)
UNNAMED_7_AD7291_I1067_VREF: C650.1(N1) U601.7(VREF)
UNNAMED_7_AD9375_I936_VCLKVCOLD: C644.1(N1) U101.M1(VCLK_VCO_LDO)
UNNAMED_7_AD9375_I936_VDDABB: C604.1(N1) C606.1(N1) R614.1(N1) U101.E5(VDDA_BB)
UNNAMED_7_AD9375_I936_VDDARXRF: C603.1(N1) C605.1(N1) R615.1(N1) U101.B1(VDDA_RXRF)
UNNAMED_7_AD9375_I936_VRXVCOLDO: C645.1(N1) U101.C8(VRX_VCO_LDO)
UNNAMED_7_AD9375_I936_VSNRXVCOL: C646.1(N1) U101.C3(VSNRX_VCO_LDO)
UNNAMED_7_AD9375_I936_VTXVCOLDO: C647.1(N1) U101.F13(VTX_VCO_LDO)
UNNAMED_8_ADP125_I911_ADJ: R739.1(N1) R740.2(N2) U702.3(ADJ)
UNNAMED_8_ADP5054_I118_BST1: C713.1(N1) U701.32(BST1)
UNNAMED_8_ADP5054_I118_BST2: C715.2(N2) U701.28(BST2)
UNNAMED_8_ADP5054_I118_BST3: C717.1(N1) U701.1(BST3)
UNNAMED_8_ADP5054_I118_BST4: C719.1(N1) U701.12(BST4)
UNNAMED_8_ADP5054_I118_COMP1: R704.2(N2) U701.40(COMP1)
UNNAMED_8_ADP5054_I118_COMP2: R707.2(N2) U701.20(COMP2)
UNNAMED_8_ADP5054_I118_COMP3: R708.2(N2) U701.47(COMP3)
UNNAMED_8_ADP5054_I118_COMP4: R711.2(N2) U701.15(COMP4)
UNNAMED_8_ADP5054_I118_DL1: Q701.5(G2) R718.2(N2) U701.31(DL1)
UNNAMED_8_ADP5054_I118_DL2: Q701.2(G1) R719.2(N2) U701.29(DL2)
UNNAMED_8_ADP5054_I118_EN1: C711.2(N2) P702.2(N2) R705.2(N2) R706.1(N1) U701.14(EN4) U701.39(EN1)
UNNAMED_8_ADP5054_I118_EN2: P702.1(N1) R702.2(N2) R703.1(N1) U701.21(EN2)
UNNAMED_8_ADP5054_I118_EN3: C712.2(N2) P702.3(N3) R709.2(N2) R710.1(N1) R712.1(N1) U701.48(EN3)
UNNAMED_8_ADP5054_I118_FB1: R714.1(N1) R715.1(N1) R716.1(N1) R717.1(N1) U701.41(FB1)
UNNAMED_8_ADP5054_I118_FB2: R720.2(N2) R721.1(N1) R722.1(N1) R723.1(N1) U701.19(FB2)
UNNAMED_8_ADP5054_I118_FB3: R724.2(N2) R725.1(N1) R726.1(N1) R727.1(N1) U701.46(FB3)
UNNAMED_8_ADP5054_I118_FB4: R728.2(N2) R729.1(N1) R730.1(N1) R731.1(N1) U701.16(FB4)
UNNAMED_8_ADP5054_I118_PWRGD: R712.2(N2) U701.17(PWRGD)
UNNAMED_8_ADP5054_I118_RT: R713.1(N1) U701.42(RT)
UNNAMED_8_ADP5054_I118_SW11: C713.2(N2) L700.1(N1) Q701.3(D2) Q701.PAD2(D2_1) U701.33(SW1_1) U701.34(SW1_2) U701.35(SW1_3)
UNNAMED_8_ADP5054_I118_SW21: C715.1(N1) L701.1(N1) Q701.6(D1) Q701.PAD1(D1_1) U701.25(SW2_1) U701.26(SW2_2) U701.27(SW2_3)
UNNAMED_8_ADP5054_I118_SW31: C717.2(N2) L702.1(N1) U701.4(SW3_1) U701.5(SW3_2)
UNNAMED_8_ADP5054_I118_SW41: C719.2(N2) L703.1(N1) U701.8(SW4_1) U701.9(SW4_2)
UNNAMED_8_ADP5054_I118_VDD: C703.2(N2) U701.43(VDD)
UNNAMED_8_CAP_I101_N1: C714.2(N2) C721.1(N1) C722.1(N1) C723.1(N1) E701.1(N1) L700.2(N2) R717.2(N2)
UNNAMED_8_CAP_I809_N2: C724.2(N2) R732.1(N1)
UNNAMED_8_CAP_I814_N2: C727.2(N2) R733.1(N1)
UNNAMED_8_CAP_I872_N2: C731.2(N2) R737.1(N1)
UNNAMED_8_CAP_I936_N2: C729.2(N2) R734.1(N1)
UNNAMED_8_CAP_I945_N1: C720.2(N2) C730.1(N1) E704.1(N1) L703.2(N2) R730.2(N2)
UNNAMED_8_CAP_I967_N1: C720.1(N1) R729.2(N2)
UNNAMED_8_CAP_I970_N1: C718.1(N1) R725.2(N2)
UNNAMED_8_CAP_I971_N1: C716.1(N1) R721.2(N2)
UNNAMED_8_CAP_I974_N1: C714.1(N1) R715.2(N2)
UNNAMED_8_CAP_I985_N2: C704.2(N2) R704.1(N1)
UNNAMED_8_CAP_I986_N2: C706.2(N2) R707.1(N1)
UNNAMED_8_CAP_I989_N2: C708.2(N2) R708.1(N1)
UNNAMED_8_CAP_I990_N2: C710.2(N2) R711.1(N1)
UNNAMED_8_CAP_I1036_N1: C718.2(N2) C728.1(N1) C739.1(N1) E703.1(N1) L702.2(N2) R726.2(N2)
UNNAMED_8_CN2P_I1027_N1: F702.1(N1) P701.1(N1)
UNNAMED_8_DIO_I32_P: CR701.A(P) F701.2(N2) F702.2(N2)
UNNAMED_8_DIOLED_I983_N: DS701.C(N) R701.2(N2)
UNNAMED_8_DIOLED_I1004_P: DS702.A(P) R735.2(N2)
UNNAMED_9_CAP_I337_N1: C801.1(N1) P801.B20(N20)
UNNAMED_9_CAP_I338_N1: C802.1(N1) P801.B21(N21)
UNNAMED_9_CAP_I852_N2: C806.2(N2) P801.D5(N5)
UNNAMED_9_CAP_I853_N2: C805.2(N2) P801.D4(N4)
UNNAMED_9_CN400PAK_I293_N2: P801.H2(N2) R801.2(N2)
UNNAMED_9_CN400PAK_I293_N10: P801.H10(N10) R802.2(N2)
UNNAMED_9_CN400PAK_I293_N11: P801.H11(N11) R803.2(N2)
UNNAMED_9_CN400PAK_I293_N13: P801.H13(N13) R804.2(N2)
UNNAMED_9_CN400PAK_I293_N14: P801.H14(N14) R805.2(N2)
UNNAMED_9_CN400PAK_I296_N12: P801.G12(N12) R806.2(N2)
UNNAMED_9_CN400PAK_I297_N18: P801.C18(N18) R816.2(N2)
UNNAMED_9_CN400PAK_I297_N19: P801.C19(N19) R817.2(N2)
UNNAMED_9_CN400PAK_I298_N11: P801.D11(N11) R810.2(N2)
UNNAMED_9_CN400PAK_I298_N14: P801.D14(N14) R811.2(N2)
UNNAMED_9_CN400PAK_I298_N15: P801.D15(N15) R812.2(N2)
UNNAMED_9_CN400PAK_I298_N17: P801.D17(N17) R813.2(N2)
UNNAMED_9_CN400PAK_I298_N18: P801.D18(N18) R814.2(N2)
UNNAMED_9_CN400PAK_I299_N1: P801.F1(N1) R807.2(N2)
UNNAMED_9_ICM24CXX_I809_E2: R822.1(N1) R823.2(N2) U801.3(E2)
VCON: C404.1(N1) R407.2(N2) Y401.1(VCON) Y402.1(VCNTRL) Y403.1(CONTROL)
VCXO_CTRL: R407.1(N1) U401.8(VCXO_VT)
VCXO_IN+: C408.2(N2) C409.2(N2) U401.11(VCXO_IN)
VCXO_IN-: C407.2(N2) R414.2(N2) U401.12(VCXO_IN_N)
VOUT1_1V3_ANLG: C601.1(N1) C602.1(N1) C724.1(N1) E601.1(N1) E602.1(N1) E603.1(N1) E604.1(N1) E605.1(N1) E606.1(N1) E607.1(N1) E608.1(N1) E609.1(N1) E610.1(N1) E611.1(N1) E612.1(N1) E613.1(N1) E701.2(N2) P703.1(N1) R601.1(N1) R612.1(N1) R614.2(N2) R615.2(N2) R716.2(N2)
VOUT2_1V3_DIG: C636.1(N1) C637.1(N1) C638.1(N1) C639.1(N1) C727.1(N1) E702.2(N2) P704.1(N1) R604.1(N1) R723.2(N2) U101.L8(VDIG_1) U101.L9(VDIG_2)
VOUT3_3V3: C641.1(N1) C729.1(N1) C736.1(N1) C737.2(N2) E703.2(N2) E705.1(N1) E706.1(N1) P705.1(N1) R608.1(N1) R727.2(N2) R735.1(N1) R736.1(N1) R807.1(N1) U101.B14(VDDA_3P3)
VOUT4_1V8: C307.1(N1) C308.1(N1) C315.1(N1) C316.1(N1) C320.1(N1) C325.1(N1) C640.1(N1) C731.1(N1) E704.2(N2) L307.2(N2) L308.1(N1) L315.2(N2) L316.1(N1) P706.1(N1) R610.1(N1) R731.2(N2) U101.D10(VDDA_1P8)

Pads without a net: P504 7 10 12 14 18 20; P801 A14 A15 A18 A19 A34 A35 A38 A39 B1 B4 B5 B8 B9 B12 B13 B16 B17 B24 B25 B28 B29 B32 B33 B36 B37 B40 C10 C11 C14 C15 C26 C27 D8 D9 D20 D21 D23 D24 D29 D33 D34 E2 E3 E6 E7 E9 E10 E12 E13 E15 E16 E18 E19 E21 E22 E24 E25 E27 E28 E30 E31 E33 E34 E36 E37 F4 F5 F7 F8 F10 F11 F13 F14 F16 F17 F19 F20 F22 F23 F25 F26 F28 F29 F31 F32 F34 F35 F37 F38 G2 G3 G6 G7 G13 G33 G34 H1 H4 H5 H16 H17 H28 H29 H31 H32 H34 H35 H37 H38 J2 J3 J6 J7 J9 J10 J12 J13 J15 J16 J18 J19 J21 J22 J24 J25 J27 J28 J30 J31 J33 J34 J36 J37 K1 K4 K5 K7 K8 K10 K11 K13 K14 K16 K17 K19 K20 K22 K23 K25 K26 K28 K29 K31 K32 K34 K35 K37 K38; T200 6; T201 6; T202 6; T203 6; T204 6; T305 6; T306 6; T307 6; T308 6; T401 2; U401 5 6 17 18 31 32 34 35 37 38 40 41 43 44 46 47 49 50 52 53 67 68 70 71; U405 6 9; U601 2 4 12; U702 6

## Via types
v1: diameter 0.508, hole 0.254, TOP to BOTTOM, 1074 vias
v2: diameter 0.406, hole 0.203, TOP to BOTTOM, 271 vias
v3: diameter 0.406, hole 0.203, L11_GND to BOTTOM, 17 vias
v4: diameter 0.508, hole 0.255, L11_GND to BOTTOM, 151 vias
v5: diameter 0.305, hole 0.152, TOP to BOTTOM, 90 vias
v6: diameter 0.305, hole 0.153, TOP to L10_SIG, 110 vias
v7: diameter 1.016, hole 0.508, TOP to BOTTOM, 9 vias
v8: diameter 0.508, hole 0.254, TOP to L10_SIG, 77 vias

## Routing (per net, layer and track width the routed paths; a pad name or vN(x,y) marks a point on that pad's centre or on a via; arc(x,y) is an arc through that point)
AGND: length 1410.3
  TOP w0.254: v5(29.24,49.18) U101.B11 v5(29.24,49.98) U101.B12 v5(29.24,50.78) U101.B13 v5(29.24,51.58) U101.A14 v5(28.44,52.38) ; v5(29.24,49.18) U101.A11 v8(28.23,49.52) ; v5(29.24,49.18) U101.B10 v6(29.24,48.38) U101.B9 ; C247.1 14.72,40.69 ; v5(34.84,46.78) U101.H7 ; U101.C9 v6(30.04,48.38) ; v5(33.24,41.18) U101.G1 v5(34.04,41.98) ; C321.1 32.6,64.15 ; v1(125.1,33.19) 125.08,33.14 125.1,33.07 125.01,32.87 C803.1 ; U101.F8 v5(33.24,46.78) ; C316.2 v1(33.19,38.3) ; U702.4 51.28,14.69 v1(51.09,14.5) ; v5(29.24,43.58) U101.B3 v5(29.24,42.78) U101.B2 v5(29.24,41.98) U101.A1 v5(28.44,41.18) ; v5(29.24,43.58) U101.A4 v5(28.44,44.38) ; v5(29.24,43.58) U101.B4 v5(29.24,44.38) U101.B5 v6(29.24,45.18) U101.B6 ; U101.M2 v6(38.04,41.98) ; U101.G11 v6(33.24,49.98) U101.G12 ; U101.F5 v6(32.44,44.38) ; v5(35.64,41.98) U101.K1 ; v5(35.64,41.98) U101.K2 v5(36.44,41.98) ; v5(35.64,41.98) U101.J2 v5(34.84,41.98) U101.H2 v5(34.04,41.98) ; U101.K1 v5(36.44,41.98) ; U101.K1 v5(36.44,41.18) ; v5(39.64,42.72) 39.64,42.78 U101.P3 ; U101.G3 v5(34.04,43.58) U101.H4 ; C314.1 37.08,28.49 ; U101.D6 v6(30.84,45.18) ; 52.33,19.48 52.59,19.48 52.84,19.22 53.35,19.22 53.73,18.84 C419.1 ; C246.1 14.66,50.21 ; U101.L2 v5(36.44,41.98) ; v5(36.44,41.98) U101.L1 ; v5(34.84,48.38) U101.H9 ; v5(39.64,41.98) U101.P2 ; v5(34.04,41.98) U101.G2 33.24,41.98 v5(33.21,41.98) ; U101.D8 v5(30.84,47.58) ; v1(75.43,56.81) 75.23,57.01 R518.2 ; U101.L14 U101.K14 ; U101.K14 v5(36.44,52.38) ; U101.K14 v5(35.64,51.58) ; U101.E10 v6(31.64,49.18) ; v5(35.64,51.58) U101.K13 v5(36.44,51.58) U101.L13 ; v5(35.64,51.58) U101.J13 v5(34.84,51.58) U101.H13 v5(34.04,51.58) ; C315.2 v1(36.41,38.3) ; v1(115.71,65.04) U403.4 ; U101.C10 v5(30.84,48.38) U101.D9 ; U101.F10 v6(32.44,48.38) ; U101.F7 v5(33.24,45.98) ; 36.77,31.04 T306.1 ; U101.G13 v5(34.04,51.58) ; v5(34.04,51.58) U101.G14 33.19,52.43 v6(33.19,52.59) ; v1(33.26,55.25) 33.07,55.06 C307.2 ; U404.3 121.53,35.11 v1(121.08,35.56) ; v5(33.24,44.38) U101.G5 ; U101.L7 v6(37.24,45.98) ; U101.D2 v5(30.84,41.98) ; U101.F4 v6(32.44,43.58) ; v5(31.64,45.98) U101.D7 ; C339.1 36.88,30.21 ; v5(37.24,49.18) U101.L10 ; v5(31.64,45.18) U101.E6 ; v5(39.61,49.11) 39.57,49.11 U101.P10 ; C212.2 14.04,40.53 ; R514.2 90.69,48.64 90.65,48.68 ; U101.E2 v6(31.64,41.98) ; v5(38.84,41.98) U101.N2 ; U101.N14 v6(38.84,52.38) ; U101.H8 34.84,47.58 v5(34.84,47.62) ; C312.1 32.58,65.13 ; C313.1 32.6,66.12 ; U101.A8 v5(28.44,47.58) ; v5(30.84,42.78) U101.D3 ; v5(34.84,49.18) U101.H10 ; U101.F9 v6(33.24,48.38) U101.G10 ; R701.1 v1(124.94,15.52) ; v6(31.64,42.78) U101.E3 ; C338.1 32.75,63.34 ; v1(36.49,55.25) 36.68,55.06 C308.2 ; U101.C5 v6(30.04,44.38) ; v5(38.04,48.38) U101.M9 ; U101.H6 v6(34.04,45.18) ; U101.H3 v6(34.04,42.78) ; U101.E9 v6(31.64,48.38) ; C322.1 37.08,27.59 ; U101.A7 28.56,46.38 v5(28.27,46.08) ; U101.P1 v6(39.64,41.18) ; U101.F6 v6(32.44,45.18) ; C326.1 37.07,29.4 ; U101.H5 v6(34.04,44.38) ; U101.F3 v6(32.44,42.78) ; U101.N7 v6(38.84,45.98)
  TOP w0.305: v1(115.86,30.98) 115.82,31.01 R821.1 ; P502.1 96.53,51.67 R516.2 ; U801.4 116.69,30 116.14,29.45 v1(116.14,29.36) 116.01,29.24 R823.1 ; R607.1 v1(55.9,27.61) ; R603.2 v1(55.9,21.51) ; v2(134.02,72.01) 133.72,71.7 R801.1 ; U405.7 122.74,60.4 v1(122.97,60.17) ; 77.75,59.53 77.29,59.99 R509.2 ; R609.1 v1(51.96,30.4) ; R507.2 75.09,67.36 75.4,67.66 ; R611.1 v1(48.91,30.4) ; R613.1 v1(45.86,30.4) ; R515.2 v1(93.52,57.64) ; U601.6 v1(47.51,24.31) U601.PAD 48.02,22.79 U601.9 ; v1(121.93,31.8) 122.03,31.8 122.53,31.3 U801.7 ; R505.1 v8(28.26,54.54) ; R605.1 v1(55.9,24.56) ; C651.2 v1(41.93,22.66) ; R508.2 77.16,67.36 77.47,67.66 ; 75.21,59.53 74.75,59.99 R506.2 ; R517.2 v1(96.26,57.64)
  TOP w0.394: C324.2 36.32,68.65 36.33,68.64 ; C323.2 v1(36.55,65.68) ; 67.33,77.96 D401.C v1(66.28,77.96) ; v2(132.75,22.48) 132.75,22.48 R504.2 ; 11.69,39.56 C208.2 ; R819.1 116.24,33.43 v1(116.47,33.19) ; P504.19 54.9,72.89 54.62,72.61 R525.1 v1(54.62,71.29) ; P504.9 v1(48.55,72.38) ; C733.1 v1(59.45,13.6) ; R719.1 82.38,28.07 82.38,28.28 v1(82.94,28.84) ; C200.2 11.14,55.98 ; 93.76,35.59 94.51,34.84 R724.1 ; 33.34,24.91 33.35,24.9 C329.2 ; P504.15 v1(52.36,72.38) ; 86.73,35.59 86.08,34.94 R714.2 ; C211.2 11.75,42.01 ; v1(79.6,22.87) 79.67,22.95 R718.1 ; v1(33.13,27.87) C328.2 ; P504.3 v1(44.74,72.38) ; v1(91.05,18.05) 90.65,18.44 R728.1 ; v1(13.01,54.17) 12.8,54.17 C202.2 ; C414.1 v1(74.89,77.78) ; v1(66.28,80.12) D402.C 67.33,80.12 ; C203.1 14.04,50.28 ; R720.1 v1(86.63,16.6) ; C428.1 92.55,69.79 ; v1(89.22,33.74) C703.1 ; P504.5 v1(46.01,72.38)
  TOP w0.508: P704.2 66.14,24.75 ; P704.2 65.06,25.83 ; P704.2 63.98,24.75 ; P704.2 65.06,23.67 ; P503.14 54.94,62.4 ; P503.14 53.86,63.48 ; P503.14 53.86,61.32 ; P503.14 52.78,62.4 ; P503.3 66.56,66.02 ; P503.3 66.56,63.86 ; P503.3 65.48,64.94 ; P503.3 67.64,64.94 ; 99.8,16.24 P706.2 ; P706.2 100.88,17.32 ; P706.2 100.88,15.16 ; P706.2 101.96,16.24 ; 83.83,63.86 P501.1 ; P501.1 82.75,64.94 ; P501.1 84.91,64.94 ; P501.1 83.83,66.02 ; P503.1 69.1,66.02 ; P503.1 70.18,64.94 ; P503.1 68.02,64.94 ; P503.1 69.1,63.86 ; J401.2 107.99,64.38 ; J401.2 106.72,63.11 ; J401.2 109.26,63.11 ; J401.2 107.99,61.84 ; J401.4 114.34,58.03 ; J401.4 113.07,56.76 ; J401.4 113.07,59.3 ; J401.4 111.8,58.03 ; J401.3 113.07,64.38 ; J401.3 111.8,63.11 ; J401.3 113.07,61.84 ; J401.3 114.34,63.11 ; 106.72,58.03 J401.5 ; J401.5 109.26,58.03 ; J401.5 107.99,56.76 ; J401.5 107.99,59.3 ; P705.2 100.88,35.26 ; P705.2 99.8,34.18 ; P705.2 100.88,33.1 ; P705.2 101.96,34.18 ; P703.2 66.14,30.7 ; P703.2 65.06,29.62 ; P703.2 65.06,31.78 ; P703.2 63.98,30.7 ; 82.75,62.4 P501.2 ; P501.2 83.83,63.48 ; P501.2 84.91,62.4 ; P501.2 83.83,61.32 ; P503.16 52.4,62.4 ; P503.16 51.32,61.32 ; P503.16 51.32,63.48 ; P503.16 50.24,62.4 ; 95.32,51.55 P502.1 ; P502.1 96.4,50.47 ; P502.1 97.48,51.55 ; 45.92,17.83 47,17.83 47,18.91
  TOP w0.762: C732.2 v1(131.45,14.4)
  TOP w1.27: P704.2 65.38,25.07 C638.2
  L2_GND w0.508: P701.2 116.2,23.61 ; P701.2 117.53,22.27 ; P701.2 114.86,22.27 ; P701.2 116.2,20.94 ; P503.14 53.86,63.48 ; P503.14 52.78,62.4 ; P503.14 54.94,62.4 ; P503.14 53.86,61.32 ; 113.07,61.84 J401.3 ; J401.3 114.34,63.11 ; J401.3 111.8,63.11 ; J401.3 113.07,64.38 ; 66.56,63.86 P503.3 ; P503.3 65.48,64.94 ; P503.3 66.56,66.02 ; P503.3 67.64,64.94 ; P705.2 101.96,34.18 ; P705.2 100.88,33.1 ; P705.2 100.88,35.26 ; P705.2 99.8,34.18 ; P502.1 96.4,52.63 ; P502.1 97.48,51.55 ; P502.1 96.4,50.47 ; P502.1 95.32,51.55 ; P704.2 65.06,25.83 ; P704.2 63.98,24.75 ; P704.2 66.14,24.75 ; P704.2 65.06,23.67 ; 99.8,16.24 P706.2 ; P706.2 100.88,17.32 ; P706.2 101.96,16.24 ; P706.2 100.88,15.16 ; 82.75,62.4 P501.2 ; P501.2 84.91,62.4 ; P501.2 83.83,63.48 ; P501.2 83.83,61.32 ; 82.75,64.94 P501.1 ; P501.1 83.83,63.86 ; P501.1 84.91,64.94 ; P501.1 83.83,66.02 ; P503.16 51.32,63.48 ; P503.16 52.4,62.4 ; P503.16 50.24,62.4 ; P503.16 51.32,61.32 ; 69.1,63.86 P503.1 ; P503.1 70.18,64.94 ; P503.1 68.02,64.94 ; P503.1 69.1,66.02 ; 106.72,58.03 J401.5 ; J401.5 107.99,56.76 ; J401.5 109.26,58.03 ; J401.5 107.99,59.3 ; 106.72,63.11 J401.2 ; J401.2 109.26,63.11 ; J401.2 107.99,61.84 ; J401.2 107.99,64.38 ; 47,16.75 47,17.83 ; 47,17.83 48.08,17.83 ; 47,17.83 47,18.91 ; 47,17.83 45.92,17.83 ; 113.07,56.76 J401.4 ; J401.4 114.34,58.03 ; J401.4 111.8,58.03 ; J401.4 113.07,59.3 ; P703.2 66.14,30.7 ; P703.2 63.98,30.7 ; P703.2 65.06,31.78 ; P703.2 65.06,29.62
  L3_PWR w0.508: P501.1 84.91,64.94 ; P501.1 82.75,64.94 ; P501.1 83.83,63.86 ; P501.1 83.83,66.02 ; 82.75,62.4 P501.2 ; P501.2 83.83,61.32 ; P501.2 84.91,62.4 ; P501.2 83.83,63.48 ; 51.32,61.32 P503.16 ; P503.16 50.24,62.4 ; P503.16 52.4,62.4 ; P503.16 51.32,63.48 ; 97.48,51.55 P502.1 96.4,52.63 ; P503.3 66.56,66.02 ; P503.3 66.56,63.86 ; P503.3 65.48,64.94 ; P503.3 67.64,64.94 ; P703.2 65.06,31.78 ; P703.2 65.06,29.62 ; P703.2 63.98,30.7 ; P703.2 66.14,30.7 ; P503.1 70.18,64.94 ; P503.1 69.1,66.02 ; P503.1 69.1,63.86 ; P503.1 68.02,64.94 ; J401.3 114.34,63.11 ; J401.3 111.8,63.11 ; J401.3 113.07,61.84 ; 116.2,20.94 P701.2 ; P701.2 114.86,22.27 ; P701.2 117.53,22.27 ; P701.2 116.2,23.61 ; P503.14 54.94,62.4 ; P503.14 53.86,63.48 ; P503.14 52.78,62.4 ; P503.14 53.86,61.32 ; 65.06,23.67 P704.2 ; P704.2 65.06,25.83 ; P704.2 66.14,24.75 ; P704.2 63.98,24.75 ; 107.99,61.84 J401.2 109.26,63.11 ; J401.4 113.07,59.3 ; J401.4 114.34,58.03 ; J401.4 111.8,58.03 ; J401.4 113.07,56.76 ; J401.5 107.99,59.3 ; J401.5 107.99,56.76 ; J401.5 109.26,58.03 ; J401.5 106.72,58.03
  L4_GND w0.508: P703.2 65.06,31.78 ; P703.2 65.06,29.62 ; P703.2 63.98,30.7 ; P703.2 66.14,30.7 ; P705.2 101.96,34.18 ; P705.2 100.88,33.1 ; P705.2 100.88,35.26 ; P705.2 99.8,34.18 ; 100.88,15.16 P706.2 ; P706.2 99.8,16.24 ; P706.2 101.96,16.24 ; P706.2 100.88,17.32 ; 114.86,22.27 P701.2 ; P701.2 116.2,20.94 ; P701.2 116.2,23.61 ; P701.2 117.53,22.27 ; P501.1 84.91,64.94 ; P501.1 83.83,66.02 ; P501.1 82.75,64.94 ; P501.1 83.83,63.86 ; 66.56,63.86 P503.3 ; P503.3 67.64,64.94 ; P503.3 66.56,66.02 ; P503.3 65.48,64.94 ; P501.2 84.91,62.4 ; P501.2 83.83,63.48 ; P501.2 82.75,62.4 ; P501.2 83.83,61.32 ; 111.8,63.11 J401.3 ; J401.3 114.34,63.11 ; J401.3 113.07,61.84 ; J401.3 113.07,64.38 ; 47,17.83 47,18.91 ; 47,17.83 48.08,17.83 ; 47,17.83 45.92,17.83 ; 47,17.83 47,16.75 ; 107.99,61.84 J401.2 ; J401.2 106.72,63.11 ; J401.2 109.26,63.11 ; J401.2 107.99,64.38 ; 95.32,51.55 P502.1 ; P502.1 96.4,52.63 ; P502.1 97.48,51.55 ; P502.1 96.4,50.47 ; 111.8,58.03 J401.4 ; J401.4 114.34,58.03 ; J401.4 113.07,56.76 ; J401.4 113.07,59.3 ; 106.72,58.03 J401.5 ; J401.5 107.99,56.76 ; J401.5 109.26,58.03 ; J401.5 107.99,59.3 ; P503.14 53.86,63.48 ; P503.14 53.86,61.32 ; P503.14 52.78,62.4 ; P503.14 54.94,62.4 ; 68.02,64.94 P503.1 ; P503.1 70.18,64.94 ; P503.1 69.1,66.02 ; P503.1 69.1,63.86 ; 65.06,23.67 P704.2 ; P704.2 63.98,24.75 ; P704.2 65.06,25.83 ; P704.2 66.14,24.75 ; P503.16 51.32,63.48 ; P503.16 51.32,61.32 ; P503.16 52.4,62.4 ; P503.16 50.24,62.4
  L5_SIG w0.508: J401.5 109.26,58.03 ; J401.5 107.99,56.76 ; J401.5 107.99,59.3 ; J401.5 106.72,58.03 ; 69.1,63.86 P503.1 ; P503.1 68.02,64.94 ; P503.1 69.1,66.02 ; 65.48,64.94 P503.3 ; P503.3 66.56,66.02 ; P503.3 67.64,64.94 ; 106.72,63.11 J401.2 ; J401.2 109.26,63.11 ; J401.2 107.99,61.84 ; 100.88,15.16 P706.2 ; P706.2 101.96,16.24 ; P706.2 99.8,16.24 ; P706.2 100.88,17.32 ; 51.32,61.32 P503.16 ; P503.16 50.24,62.4 ; P503.16 52.4,62.4 ; 99.8,34.18 P705.2 ; P705.2 100.88,33.1 ; P705.2 101.96,34.18 ; P705.2 100.88,35.26 ; 53.86,61.32 P503.14 ; P503.14 52.78,62.4 ; P503.14 54.94,62.4 ; 45.92,17.83 47,17.83 ; 47,17.83 47,18.91 ; 47,17.83 48.08,17.83 ; 47,17.83 47,16.75 ; P501.1 83.83,66.02 ; P501.1 84.91,64.94 ; P501.1 83.83,63.86 ; 111.8,63.11 J401.3 ; J401.3 113.07,61.84 ; J401.3 114.34,63.11 ; P704.2 66.14,24.75 ; P704.2 63.98,24.75 ; P704.2 65.06,23.67 ; P704.2 65.06,25.83 ; 111.8,58.03 J401.4 ; J401.4 113.07,56.76 ; J401.4 114.34,58.03 ; J401.4 113.07,59.3 ; 95.32,51.55 P502.1 97.48,51.55 ; P501.2 84.91,62.4 ; P501.2 83.83,63.48 ; P501.2 83.83,61.32 ; P501.2 82.75,62.4 ; P701.2 116.2,23.61 ; P701.2 114.86,22.27 ; P701.2 116.2,20.94 ; P701.2 117.53,22.27 ; 65.06,31.78 P703.2 66.14,30.7
  L6_GND w0.508: 100.88,15.16 P706.2 ; P706.2 101.96,16.24 ; P706.2 99.8,16.24 ; P706.2 100.88,17.32 ; 111.8,63.11 J401.3 ; J401.3 114.34,63.11 ; J401.3 113.07,61.84 ; J401.3 113.07,64.38 ; 82.75,62.4 P501.2 ; P501.2 83.83,61.32 ; P501.2 83.83,63.48 ; P501.2 84.91,62.4 ; 65.06,29.62 P703.2 ; P703.2 66.14,30.7 ; P703.2 65.06,31.78 ; P703.2 63.98,30.7 ; 100.88,33.1 P705.2 ; P705.2 100.88,35.26 ; P705.2 101.96,34.18 ; P705.2 99.8,34.18 ; 83.83,63.86 P501.1 ; P501.1 82.75,64.94 ; P501.1 84.91,64.94 ; P501.1 83.83,66.02 ; P503.1 70.18,64.94 ; P503.1 69.1,63.86 ; P503.1 68.02,64.94 ; P503.1 69.1,66.02 ; 95.32,51.55 P502.1 ; P502.1 97.48,51.55 ; P502.1 96.4,50.47 ; P502.1 96.4,52.63 ; 107.99,56.76 J401.5 ; J401.5 106.72,58.03 ; J401.5 107.99,59.3 ; J401.5 109.26,58.03 ; P503.3 67.64,64.94 ; P503.3 66.56,66.02 ; P503.3 66.56,63.86 ; P503.3 65.48,64.94 ; 50.24,62.4 P503.16 ; P503.16 51.32,63.48 ; P503.16 52.4,62.4 ; P503.16 51.32,61.32 ; J401.2 109.26,63.11 ; J401.2 107.99,64.38 ; J401.2 106.72,63.11 ; J401.2 107.99,61.84 ; P503.14 54.94,62.4 ; P503.14 53.86,61.32 ; P503.14 53.86,63.48 ; P503.14 52.78,62.4 ; 47,17.83 47,18.91 ; 47,17.83 47,16.75 ; 47,17.83 48.08,17.83 ; 47,17.83 45.92,17.83 ; P701.2 116.2,23.61 ; P701.2 114.86,22.27 ; P701.2 116.2,20.94 ; P701.2 117.53,22.27 ; 113.07,56.76 J401.4 ; J401.4 113.07,59.3 ; J401.4 114.34,58.03 ; J401.4 111.8,58.03 ; 63.98,24.75 P704.2 ; P704.2 65.06,23.67 ; P704.2 65.06,25.83 ; P704.2 66.14,24.75
  L7_SIG w0.152: 34.3,49.96 34.84,49.42 v5(34.84,49.18)
  L7_SIG w0.508: 65.06,29.62 P703.2 ; P703.2 63.98,30.7 ; P703.2 66.14,30.7 ; P703.2 65.06,31.78 ; 63.98,24.75 P704.2 ; P704.2 65.06,23.67 ; P704.2 66.14,24.75 ; P704.2 65.06,25.83 ; P503.14 54.94,62.4 ; P503.14 53.86,63.48 ; P503.14 53.86,61.32 ; P503.14 52.78,62.4 ; P706.2 101.96,16.24 ; P706.2 100.88,17.32 ; P706.2 100.88,15.16 ; P706.2 99.8,16.24 ; 65.48,64.94 P503.3 ; P503.3 67.64,64.94 ; P503.3 66.56,66.02 ; P503.3 66.56,63.86 ; 96.4,50.47 P502.1 ; P502.1 96.4,52.63 ; P502.1 95.32,51.55 ; P502.1 97.48,51.55 ; 99.8,34.18 P705.2 ; P705.2 101.96,34.18 ; P705.2 100.88,33.1 ; P705.2 100.88,35.26 ; P501.1 84.91,64.94 ; P501.1 82.75,64.94 ; P501.1 83.83,63.86 ; P501.1 83.83,66.02 ; 47,16.75 47,17.83 ; 47,17.83 48.08,17.83 ; 47,17.83 47,18.91 ; 47,17.83 45.92,17.83 ; P701.2 116.2,23.61 ; P701.2 116.2,20.94 ; P701.2 114.86,22.27 ; P701.2 117.53,22.27 ; 106.72,63.11 J401.2 ; J401.2 109.26,63.11 ; J401.2 107.99,61.84 ; J401.2 107.99,64.38 ; 82.75,62.4 P501.2 ; P501.2 83.83,61.32 ; P501.2 84.91,62.4 ; P501.2 83.83,63.48 ; P503.1 70.18,64.94 ; P503.1 68.02,64.94 ; P503.1 69.1,66.02 ; P503.1 69.1,63.86 ; J401.3 113.07,64.38 ; J401.3 111.8,63.11 ; J401.3 114.34,63.11 ; J401.3 113.07,61.84 ; 50.24,62.4 P503.16 ; P503.16 52.4,62.4 ; P503.16 51.32,63.48 ; P503.16 51.32,61.32 ; J401.5 109.26,58.03 ; J401.5 106.72,58.03 ; J401.5 107.99,59.3 ; J401.4 114.34,58.03 ; J401.4 113.07,59.3 ; J401.4 111.8,58.03
  L8_SIG w0.152: 33.82,47.13 33.63,46.94 33.63,46.75 33.54,46.66
  L8_SIG w0.508: P503.14 53.86,63.48 ; P503.14 53.86,61.32 ; P503.14 54.94,62.4 ; P704.2 66.14,24.75 ; P704.2 63.98,24.75 ; P704.2 65.06,25.83 ; 47,17.83 47,18.91 ; 47,17.83 48.08,17.83 ; 47,17.83 45.92,17.83 ; 47,17.83 47,16.75 ; P703.2 65.06,31.78 ; P703.2 63.98,30.7 ; P703.2 66.14,30.7 ; 107.99,61.84 J401.2 ; J401.2 106.72,63.11 ; J401.2 109.26,63.11 ; J401.2 107.99,64.38 ; P706.2 101.96,16.24 ; P706.2 100.88,17.32 ; P706.2 99.8,16.24 ; 84.91,64.94 P501.1 82.75,64.94 ; 106.72,58.03 J401.5 ; J401.5 107.99,59.3 ; J401.5 109.26,58.03 ; J401.5 107.99,56.76 ; J401.4 114.34,58.03 ; J401.4 113.07,56.76 ; J401.4 111.8,58.03 ; J401.4 113.07,59.3 ; 117.53,22.27 P701.2 116.2,20.94 ; 96.4,50.47 P502.1 ; P502.1 97.48,51.55 ; P502.1 95.32,51.55 ; 84.91,62.4 P501.2 82.75,62.4 ; 65.48,64.94 P503.3 66.56,63.86 ; 113.07,61.84 J401.3 ; J401.3 114.34,63.11 ; J401.3 113.07,64.38 ; J401.3 111.8,63.11 ; P503.1 69.1,66.02 ; P503.1 70.18,64.94 ; P503.1 69.1,63.86 ; 51.32,61.32 P503.16 ; P503.16 51.32,63.48 ; P503.16 50.24,62.4 ; P705.2 100.88,35.26 ; P705.2 101.96,34.18 ; P705.2 99.8,34.18
  L9_GND w0.508: 113.07,56.76 J401.4 ; J401.4 114.34,58.03 ; J401.4 113.07,59.3 ; J401.4 111.8,58.03 ; J401.3 113.07,64.38 ; J401.3 113.07,61.84 ; J401.3 111.8,63.11 ; J401.3 114.34,63.11 ; 82.75,64.94 P501.1 ; P501.1 83.83,66.02 ; P501.1 84.91,64.94 ; P501.1 83.83,63.86 ; 47,17.83 48.08,17.83 ; 47,17.83 47,18.91 ; 47,17.83 47,16.75 ; 47,17.83 45.92,17.83 ; 99.8,16.24 P706.2 ; P706.2 101.96,16.24 ; P706.2 100.88,15.16 ; P706.2 100.88,17.32 ; P704.2 66.14,24.75 ; P704.2 65.06,25.83 ; P704.2 65.06,23.67 ; P704.2 63.98,24.75 ; 50.24,62.4 P503.16 ; P503.16 51.32,61.32 ; P503.16 52.4,62.4 ; P503.16 51.32,63.48 ; J401.5 107.99,59.3 ; J401.5 107.99,56.76 ; J401.5 106.72,58.03 ; J401.5 109.26,58.03 ; 107.99,61.84 J401.2 ; J401.2 109.26,63.11 ; J401.2 106.72,63.11 ; J401.2 107.99,64.38 ; 52.78,62.4 P503.14 ; P503.14 53.86,63.48 ; P503.14 54.94,62.4 ; P503.14 53.86,61.32 ; P705.2 100.88,35.26 ; P705.2 99.8,34.18 ; P705.2 100.88,33.1 ; P705.2 101.96,34.18 ; 65.48,64.94 P503.3 ; P503.3 66.56,66.02 ; P503.3 67.64,64.94 ; P503.3 66.56,63.86 ; P501.2 84.91,62.4 ; P501.2 83.83,61.32 ; P501.2 82.75,62.4 ; P501.2 83.83,63.48 ; 116.2,20.94 P701.2 ; P701.2 114.86,22.27 ; P701.2 116.2,23.61 ; P701.2 117.53,22.27 ; P503.1 69.1,66.02 ; P503.1 70.18,64.94 ; P503.1 69.1,63.86 ; P503.1 68.02,64.94 ; 96.4,50.47 P502.1 ; P502.1 97.48,51.55 ; P502.1 96.4,52.63 ; P502.1 95.32,51.55 ; P703.2 66.14,30.7 ; P703.2 63.98,30.7 ; P703.2 65.06,31.78 ; P703.2 65.06,29.62
  L10_SIG w0.127: 29.09,48.05 29.23,47.92 29.38,47.92 29.73,47.57 29.73,47.42
  L10_SIG w0.508: 63.98,30.7 P703.2 ; P703.2 66.14,30.7 ; P703.2 65.06,29.62 ; P703.2 65.06,31.78 ; 65.48,64.94 P503.3 ; P503.3 66.56,63.86 ; P503.3 66.56,66.02 ; P503.3 67.64,64.94 ; P503.1 69.1,66.02 ; P503.1 68.02,64.94 ; P503.1 70.18,64.94 ; P503.1 69.1,63.86 ; 113.07,56.76 J401.4 ; J401.4 113.07,59.3 ; J401.4 114.34,58.03 ; J401.4 111.8,58.03 ; 113.07,61.84 J401.3 ; J401.3 111.8,63.11 ; J401.3 114.34,63.11 ; J401.3 113.07,64.38 ; P701.2 117.53,22.27 ; P701.2 116.2,23.61 ; P701.2 114.86,22.27 ; P701.2 116.2,20.94 ; 107.99,56.76 J401.5 ; J401.5 107.99,59.3 ; J401.5 109.26,58.03 ; J401.5 106.72,58.03 ; 83.83,61.32 P501.2 ; P501.2 82.75,62.4 ; P501.2 84.91,62.4 ; P501.2 83.83,63.48 ; 53.86,61.32 P503.14 ; P503.14 53.86,63.48 ; P503.14 52.78,62.4 ; 95.32,51.55 P502.1 ; P502.1 97.48,51.55 ; P502.1 96.4,50.47 ; P502.1 96.4,52.63 ; 107.99,61.84 J401.2 ; J401.2 106.72,63.11 ; J401.2 107.99,64.38 ; J401.2 109.26,63.11 ; 47,16.75 47,17.83 ; 47,17.83 47,18.91 ; 47,17.83 48.08,17.83 ; 47,17.83 45.92,17.83 ; 82.75,64.94 P501.1 83.83,63.86 ; 100.88,35.26 P705.2 99.8,34.18 ; 100.88,15.16 P706.2 ; P706.2 101.96,16.24 ; P706.2 99.8,16.24 ; P706.2 100.88,17.32 ; 51.32,63.48 P503.16 52.4,62.4
  L11_GND w0.508: 100.88,33.1 P705.2 ; P705.2 100.88,35.26 ; P705.2 99.8,34.18 ; P705.2 101.96,34.18 ; J401.5 107.99,59.3 ; J401.5 107.99,56.76 ; J401.5 109.26,58.03 ; J401.5 106.72,58.03 ; 52.78,62.4 P503.14 ; P503.14 53.86,61.32 ; P503.14 54.94,62.4 ; P503.14 53.86,63.48 ; P502.1 97.48,51.55 ; P502.1 95.32,51.55 ; P502.1 96.4,50.47 ; P502.1 96.4,52.63 ; 51.32,61.32 P503.16 ; P503.16 52.4,62.4 ; P503.16 51.32,63.48 ; P503.16 50.24,62.4 ; P701.2 117.53,22.27 ; P701.2 114.86,22.27 ; P701.2 116.2,23.61 ; P701.2 116.2,20.94 ; 113.07,61.84 J401.3 ; J401.3 113.07,64.38 ; J401.3 114.34,63.11 ; J401.3 111.8,63.11 ; 69.1,63.86 P503.1 ; P503.1 70.18,64.94 ; P503.1 68.02,64.94 ; P503.1 69.1,66.02 ; P706.2 101.96,16.24 ; P706.2 100.88,15.16 ; P706.2 99.8,16.24 ; P706.2 100.88,17.32 ; J401.4 113.07,59.3 ; J401.4 113.07,56.76 ; J401.4 114.34,58.03 ; J401.4 111.8,58.03 ; 106.72,63.11 J401.2 ; J401.2 107.99,64.38 ; J401.2 107.99,61.84 ; J401.2 109.26,63.11 ; 65.06,23.67 P704.2 ; P704.2 63.98,24.75 ; P704.2 66.14,24.75 ; P704.2 65.06,25.83 ; P501.2 83.83,63.48 ; P501.2 82.75,62.4 ; P501.2 84.91,62.4 ; P501.2 83.83,61.32 ; 65.48,64.94 P503.3 ; P503.3 66.56,63.86 ; P503.3 66.56,66.02 ; P503.3 67.64,64.94 ; 47,17.83 47,18.91 ; 47,17.83 48.08,17.83 ; 47,17.83 45.92,17.83 ; 47,17.83 47,16.75 ; 63.98,30.7 P703.2 ; P703.2 65.06,29.62 ; P703.2 66.14,30.7 ; P703.2 65.06,31.78 ; 83.83,63.86 P501.1 ; P501.1 82.75,64.94 ; P501.1 84.91,64.94 ; P501.1 83.83,66.02
  L12_PWR w0.508: J401.5 109.26,58.03 ; J401.5 106.72,58.03 ; J401.5 107.99,56.76 ; J401.5 107.99,59.3 ; 51.32,61.32 P503.16 ; P503.16 52.4,62.4 ; P503.16 50.24,62.4 ; P503.16 51.32,63.48 ; 63.98,24.75 P704.2 65.52,25.81 ; 107.99,61.84 J401.2 ; J401.2 109.26,63.11 ; J401.2 106.72,63.11 ; J401.2 107.99,64.38 ; 100.88,33.1 P705.2 ; P705.2 101.96,34.18 ; P705.2 99.8,34.18 ; P705.2 100.88,35.26 ; P503.14 54.94,62.4 ; P503.14 53.86,61.32 ; P503.14 53.86,63.48 ; P503.14 52.78,62.4 ; P706.2 101.96,16.24 ; P706.2 100.88,15.16 ; P706.2 99.8,16.24 ; P706.2 100.88,17.32 ; 113.07,56.76 J401.4 ; J401.4 111.8,58.03 ; J401.4 113.07,59.3 ; J401.4 114.34,58.03 ; 68.02,64.94 P503.1 ; P503.1 70.18,64.94 ; P503.1 69.1,66.02 ; P503.1 69.1,63.86 ; 111.8,63.11 J401.3 ; J401.3 113.07,61.84 ; J401.3 113.07,64.38 ; J401.3 114.34,63.11 ; 82.75,62.4 P501.2 ; P501.2 83.83,61.32 ; P501.2 84.91,62.4 ; P501.2 83.83,63.48 ; 65.48,64.94 P503.3 ; P503.3 66.56,63.86 ; P503.3 67.64,64.94 ; P503.3 66.56,66.02 ; P501.1 83.83,66.02 ; P501.1 82.75,64.94 ; P501.1 84.91,64.94 ; P501.1 83.83,63.86 ; 65.06,31.78 P703.2 66.14,30.7
  L13_GND w0.508: P503.14 53.86,63.48 ; P503.14 52.78,62.4 ; P503.14 53.86,61.32 ; P503.14 54.94,62.4 ; 45.92,17.83 47,17.83 ; 47,17.83 47,16.75 ; 47,17.83 48.08,17.83 ; 47,17.83 47,18.91 ; 114.86,22.27 P701.2 ; P701.2 117.53,22.27 ; P701.2 116.2,23.61 ; P701.2 116.2,20.94 ; P704.2 66.14,24.75 ; P704.2 63.98,24.75 ; P704.2 65.06,23.67 ; P704.2 65.06,25.83 ; P703.2 66.14,30.7 ; P703.2 63.98,30.7 ; P703.2 65.06,31.78 ; P703.2 65.06,29.62 ; 95.32,51.55 P502.1 ; P502.1 97.48,51.55 ; P502.1 96.4,52.63 ; P502.1 96.4,50.47 ; 83.83,63.86 P501.1 ; P501.1 82.75,64.94 ; P501.1 83.83,66.02 ; P501.1 84.91,64.94 ; 69.1,63.86 P503.1 ; P503.1 70.18,64.94 ; P503.1 69.1,66.02 ; P503.1 68.02,64.94 ; J401.3 114.34,63.11 ; J401.3 113.07,64.38 ; J401.3 111.8,63.11 ; J401.3 113.07,61.84 ; P706.2 100.88,17.32 ; P706.2 100.88,15.16 ; P706.2 99.8,16.24 ; P706.2 101.96,16.24 ; 99.8,34.18 P705.2 ; P705.2 100.88,33.1 ; P705.2 100.88,35.26 ; P705.2 101.96,34.18 ; 107.99,61.84 J401.2 ; J401.2 109.26,63.11 ; J401.2 106.72,63.11 ; J401.2 107.99,64.38 ; J401.5 107.99,59.3 ; J401.5 109.26,58.03 ; J401.5 107.99,56.76 ; J401.5 106.72,58.03 ; 50.24,62.4 P503.16 ; P503.16 51.32,61.32 ; P503.16 51.32,63.48 ; P503.16 52.4,62.4 ; J401.4 113.07,59.3 ; J401.4 113.07,56.76 ; J401.4 111.8,58.03 ; J401.4 114.34,58.03 ; 66.56,63.86 P503.3 ; P503.3 65.48,64.94 ; P503.3 66.56,66.02 ; P503.3 67.64,64.94 ; 83.83,61.32 P501.2 ; P501.2 83.83,63.48 ; P501.2 84.91,62.4 ; P501.2 82.75,62.4
  BOTTOM w0.127: 15.37,65.52 15.68,65.67 15.57,65.62 ; 23.99,17.99 23.69,18.15 23.79,18.1
  BOTTOM w0.203: 30.85,44.27 30.72,44.14 30.72,43.99 30.62,43.89 30.62,43.22 30.87,42.97 31,42.97 ; C330.2 v3(16.69,46.06) ; C331.2 v3(19.67,46.02) ; 26.03,66.75 v1(25.44,66.54) ; 36.63,53.26 37.05,53.68 40.14,53.68 40.85,53.65 ; 27.04,63.96 v1(26.45,63.74)
  BOTTOM w0.254: v1(17.33,34.68) 17.41,34.68 17.41,34.62 17.43,34.63 18.03,34.21 ; U701.30 85.21,25.62 v1(85.46,25.87) ; v5(28.44,44.38) 28.46,44.39 C621.2 ; v1(55.16,67.22) 54.49,66.55 C526.2 ; U401.13 87.54,69.82 88.09,70.37 v1(88.09,71.09) ; 62.11,66.85 62.11,66.88 v1(61.83,67.16) ; 62.11,66.85 C524.2 ; 62.11,66.85 61.8,67.16 ; R417.1 v1(98.3,77.04) ; 70.37,61.64 69.73,61.01 C528.2 ; U701.2 92.06,28.12 v1(92.32,27.86) 92.07,27.62 U701.3 ; C531.2 62.75,61.29 62.75,61.64 ; C619.2 33.08,45.81 v5(33.24,45.98) ; 67.83,61.64 67.19,61.01 C529.2 ; C248.1 21.04,62.1 ; v1(57.18,67.43) 57.03,67.27 C525.2 ; C250.1 23.58,24.58 ; C220.2 23.31,24 ; C505.2 81.99,60.93 v1(82.59,61.53) ; 20.45,62.49 20.49,62.55 20.5,62.56 ; C249.1 17.54,33.45 ; C649.2 49.54,22.27 v1(49.55,22.28) ; C523.2 64.65,66.88 v1(64.37,67.16) ; C640.2 30.22,50.68 v4(30.03,50.87) ; v4(37.24,50.72) 37.41,50.9 C642.2 ; C413.2 v1(86.95,64.74) ; v4(37.78,49.53) 37.78,49.52 C654.2 ; C532.2 59.57,61.01 60.21,61.64 ; C530.2 64.65,61.01 65.29,61.64 ; v5(36.44,41.98) 36.5,42.03 C609.2 ; C615.2 v4(35.33,44.07) ; U401.4 92.04,68.63 92.04,69.57 91.9,69.7 v1(91.9,71.09) ; C629.2 29.34,44.28 v5(29.24,44.38) ; 79.94,61.5 79.38,60.95 C503.2 ; C645.2 30.3,48.37 30.62,48.05 ; U701.10 92.06,24.12 v1(92.32,23.86) 92.07,23.62 U701.11 ; v1(82.33,25.87) v1(82.33,25.11) 82.1,24.87 Q701.4 81.42,25.31 v1(81.7,25.59) ; v5(34.04,41.98) 33.97,42.05 C610.2 ; v1(29.43,38.53) 29.5,38.53 29.89,38.92 C603.2 29.87,39.49 C605.2 ; C527.2 52.42,66.37 v1(53.14,67.09) ; v1(89.36,71.09) 89.36,70.14 89.54,69.96 U401.9 ; C644.2 v4(38.88,42.83) ; C606.2 32.1,43.25 v4(32.01,43.25) ; C627.2 v4(35.19,46.18) ; C236.2 17.08,33.01 ; C625.2 v4(28.94,47.82) ; R419.2 98.44,78.89 ; C504.2 v1(79.38,67.03) ; C506.2 v1(81.92,67.03)
  BOTTOM w0.305: C617.2 39.63,41.96 v5(39.64,41.98) ; v4(30.6,51.3) C641.2 ; C613.2 41.03,47.16 v4(41.42,47.16) ; 41.37,35.84 v4(41.36,35.84) ; 34.81,49.07 34.74,49.01 C631.2 ; Q701.1 v1(79.6,22.87) ; U402.2 v1(76.76,79.04) ; C219.2 25.61,20.64 ; C616.2 v4(41,42.97) ; v4(38.72,47.66) 38.67,47.72 C637.2 ; C633.2 v3(29.85,53.51)
  BOTTOM w0.381: v1(93.76,33.87) C712.1 R710.2 ; C701.2 83.81,35.21 84.19,35.59 ; 86.73,35.59 87.45,34.87 C704.1 ; C620.2 v1(25.79,47.77)
  BOTTOM w0.394: P801.E20 P801.F21 v2(137.83,46.61) ; v2(137.83,41.53) P801.E26 ; P801.E26 137.88,40.31 v2(137.83,40.31) ; P801.E26 P801.D25 ; P801.G14 v2(136.56,55.5) P801.F15 ; P801.B22 v2(142.91,45.34) P801.B23 ; P801.C40 v2(141.64,22.48) ; v4(40.03,49.02) 40.03,49.91 C653.2 ; P801.A17 143.67,52.32 144.37,51.63 v2(144.39,51.63) ; P801.J35 v2(134.02,28.83) ; P801.J26 v2(132.75,41.53) ; T307.5 v3(21.59,44.96) ; P801.B11 v2(142.91,59.31) ; P801.A1 v2(144.18,72.01) ; P801.J40 v2(132.75,22.48) ; C612.2 39.2,45.55 v4(39.2,44.83) ; C706.1 v1(86.63,16.6) ; P801.H36 v2(134.02,27.56) ; P801.B26 v2(142.91,40.26) ; P801.K18 P801.J17 v2(132.75,52.96) ; P801.K21 v2(132.75,46.61) ; P801.K39 v2(131.48,23.75) ; P801.K2 v2(131.48,70.74) P801.K3 ; P801.F33 v2(137.83,31.37) ; P801.H33 v2(135.29,31.37) ; P801.B38 v2(142.91,25.02) ; v1(99.15,79.96) R418.2 ; C405.1 v1(109.44,77.5) ; P801.J8 v2(132.75,64.39) ; v2(144.39,52.9) 144.37,52.9 143.67,53.59 P801.A16 ; P801.A32 v2(144.18,32.64) ; v2(145.91,46.55) 144.25,46.55 P801.A21 ; P801.F27 v2(137.83,38.99) ; P801.B14 v2(142.91,55.5) ; v2(140.37,37.72) P801.D28 v2(139.1,38.99) ; C235.2 v4(18.88,29.24) ; v2(144.38,56.73) 143.7,57.4 P801.A13 ; P801.G5 v2(136.56,66.93) ; P801.B2 v2(141.64,72.01) P801.C1 ; P801.D16 P801.C16 v2(141.64,54.23) ; P801.C12 P801.C13 v2(141.64,56.77) ; P801.G32 v2(136.56,32.64) ; v2(142.89,69.48) 142.89,69.49 P801.B3 ; P801.H18 v2(134.02,51.69) ; v2(144.54,42.79) 143.89,43.43 P801.A24 ; P801.H12 v2(134.02,59.31) P801.J11 ; v2(137.88,35.2) 137.81,35.2 P801.F30 ; R428.2 104.04,72.15 103.9,72.29 v1(103.89,72.29) ; v2(132.75,45.34) P801.J23 v2(134.02,44.07) P801.H24 ; v2(144.51,41.7) 144.01,41.7 P801.A25 ; C626.2 18.62,54.34 v1(18.62,54.34) ; P801.C33 v2(141.64,31.37) ; v2(132.75,69.47) P801.J4 P801.J5 ; P801.B35 v2(142.91,28.83) ; P801.H6 v2(134.02,66.93) ; v1(99.17,79) 99.06,78.89 98.44,78.89 ; P801.J38 v2(134.02,25.02) ; P801.G20 v2(136.56,47.88) ; 23.93,18.19 24.2,18.05 C217.2 ; P801.E5 v2(139.1,66.93) P801.D6 ; P801.D13 v2(139.1,58.04) ; P801.K6 v2(131.48,66.93) ; C647.2 36.86,62.77 ; 15.68,65.44 15.64,65.46 15.61,65.41 ; R403.1 v1(97.18,65.56) ; P801.E40 v2(139.1,22.48) ; P801.A36 v2(144.18,27.56) ; P801.H21 v2(134.02,47.88) P801.J20 v2(132.75,49.15) ; P801.E14 v2(137.83,56.77) ; P801.K33 v2(131.48,31.37) ; P801.F12 v2(137.83,58.04) ; R402.1 v1(104.68,65.55) ; P801.K12 v2(131.48,58.04) ; P801.A33 v2(144.18,31.37) ; T308.2 v1(29.1,62.67) ; C708.1 91.09,34.87 91.81,35.59 ; v1(84.57,16.9) 84.9,17.23 C705.2 ; P801.A28 144.19,37.72 v2(144.28,37.72) ; P801.G11 v2(136.56,59.31) ; P801.J32 v2(134.02,32.64) ; P801.J14 v2(134.02,55.5) ; P801.C38 v2(141.64,25.02) ; v4(36.84,45.05) 36.71,45.19 C636.2 ; C420.2 v1(94.54,79.66) ; C225.2 15.78,65.56 15.3,65.32 15.58,65.45 ; v1(97.18,61.01) R404.2 ; P801.B27 v2(142.91,38.99) ; R401.1 v1(105.81,63.78) ; P801.A8 143.66,63.75 v2(144.36,64.45) ; P801.K30 v2(131.48,35.18) ; P801.J1 v2(134.02,72.01) ; T308.5 v1(26.3,61.63) ; v2(140.36,70.71) 140.35,70.71 P801.D3 P801.C4 v2(141.64,68.2) P801.C5 ; P801.G8 P801.H9 v2(135.29,61.85) ; C635.2 36.1,50.75 ; C233.2 v4(16.77,27.03) ; P801.D19 v2(140.37,49.15) ; P801.E4 137.86,68.22 v2(137.85,68.22) ; v2(141.64,41.53) P801.C25 P801.C24 ; P801.A37 v2(144.18,26.29) ; v2(140.37,63.12) P801.C8 ; v1(122.99,72.16) R409.1 ; v1(90,16.6) C710.1 ; v2(144.38,58) 143.7,58.67 P801.A12 ; v1(122.53,71.42) Y402.3 Y403.2 Y401.3 ; P801.H30 v2(134.02,35.18) ; P801.G35 v2(136.56,30.1) ; P801.B30 v2(142.91,35.18) ; P801.B39 v2(142.91,23.75) ; P801.E1 v2(139.1,73.28) ; P801.G38 v2(136.56,25.02) ; C618.2 v4(44.56,42.97) ; P801.D22 v2(140.37,46.61) P801.C21 P801.C20 ; P801.D2 v2(140.37,72.01) ; P801.B31 v2(142.91,33.91) ; P801.C17 P801.B18 v2(142.91,51.69) ; v2(136.56,51.69) P801.F18 P801.E17 ; P801.B15 v2(142.91,54.23) ; P801.G17 v2(135.29,52.96) ; P801.B10 v2(142.91,60.58) ; P801.C32 v2(141.64,32.64) ; P801.H3 134.63,70.1 v2(134.03,69.5) ; v2(139.1,63.12) P801.E8 ; P801.F3 v2(137.83,69.47) ; P801.G4 135.87,68.83 v2(135.28,69.42) ; P801.K9 v2(131.52,61.88) ; v2(137.83,61.85) P801.F9 ; P801.B34 v2(142.91,30.1) ; v1(13.06,61.08) 13.06,61.07 C630.2 ; v1(86.6,33.69) R706.2 ; P801.B19 P801.A20 143.92,48.51 v2(144.31,48.91) ; P801.K15 v2(131.48,55.5) ; P801.K27 v2(131.48,38.99) ; v2(145.22,61.81) 144.55,62.48 P801.A9 ; C702.1 89.7,33.26 v1(89.22,33.74) 88.63,33.16 R713.2 ; C406.1 v1(104.1,73.18) ; v2(139.1,64.39) P801.D7 ; P801.G40 v2(136.56,22.48) ; P801.C28 v2(141.64,37.72) ; P801.H15 v2(134.02,54.23) ; P801.G29 v2(136.56,36.45) ; P801.G26 v2(136.56,40.26) ; v1(127.14,73.22) C738.1 ; P801.C36 v2(141.64,27.56) ; P801.K36 v2(131.48,27.56) ; P801.A4 v2(144.18,68.2) ; C711.1 v1(92.02,21.51) ; T307.2 v3(21.59,48.23) ; v2(135.29,73.28) P801.G1 ; C227.2 v4(16.57,62.63) ; P801.F6 v2(137.83,65.66) ; P801.C29 v2(141.64,36.45) ; v1(91.44,67.36) C410.1 C411.1 ; P801.E38 v2(139.1,25.02) ; P801.E23 v2(137.83,45.34) ; P801.D10 v2(140.37,60.58) ; C404.2 v1(123.8,75.51) ; P801.J29 v2(134.02,36.45) ; P801.A29 v2(144.18,36.45) ; P801.F39 v2(137.83,23.75) ; P801.A40 v2(144.18,22.48) ; P801.F24 v2(137.83,42.8) ; P801.F2 v2(136.56,70.74) ; P801.K24 132.75,44.07 v2(132.75,44.08) ; P801.D37 v2(140.37,26.29) ; C737.1 100.54,33.84 P705.2 ; P801.B6 v2(142.91,65.66) P801.B7 ; P801.A5 v2(144.18,66.93) ; v2(141.64,61.85) P801.C9 v2(140.37,61.85) ; P801.F36 v2(137.83,27.56) ; P801.D39 v2(140.37,23.75) ; v2(139.1,60.58) P801.E11 ; P801.E35 v2(139.1,28.83) ; P801.H27 v2(134.02,40.26) ; P801.G23 v2(136.56,44.07) ; P801.E32 v2(139.1,32.64) ; P801.E29 v2(139.1,36.45) ; P801.H39 v2(135.29,23.75)
  BOTTOM w0.508: C701.2 82.88,34.06 v1(82.54,33.72) v1(82.54,34.4) ; 52.78,62.4 P503.14 ; P503.14 53.86,61.32 ; P503.14 53.86,63.48 ; P503.14 54.94,62.4 ; P701.2 117.53,22.27 ; P701.2 116.2,20.94 ; P701.2 114.86,22.27 ; P701.2 116.2,23.61 ; 99.8,34.18 P705.2 100.88,35.26 ; J401.3 113.07,64.38 ; J401.3 114.34,63.11 ; J401.3 111.8,63.11 ; J401.3 113.07,61.84 ; 65.06,31.78 P703.2 63.98,30.7 ; 50.24,62.4 P503.16 ; P503.16 51.32,61.32 ; P503.16 52.4,62.4 ; P503.16 51.32,63.48 ; 106.72,63.11 J401.2 ; J401.2 107.99,61.84 ; J401.2 109.26,63.11 ; J401.2 107.99,64.38 ; P501.1 84.91,64.94 ; P501.1 83.83,66.02 ; P501.1 83.83,63.86 ; P501.1 82.75,64.94 ; v1(71.82,32.12) 71.83,32.11 R732.2 ; v1(84.57,16.9) v1(85.31,16.9) ; 65.48,64.94 P503.3 ; P503.3 66.56,66.02 ; P503.3 67.64,64.94 ; P503.3 66.56,63.86 ; 65.06,23.67 P704.2 ; P704.2 65.06,25.83 ; P704.2 66.14,24.75 ; P704.2 63.98,24.75 ; P502.1 96.4,52.63 ; P502.1 97.48,51.55 ; P502.1 95.32,51.55 ; 47,17.83 48.08,17.83 ; 47,17.83 45.92,17.83 ; 47,17.83 47,16.75 ; 47,17.83 47,18.91 ; J401.4 113.07,59.3 ; J401.4 111.8,58.03 ; J401.4 114.34,58.03 ; P501.2 83.83,63.48 ; P501.2 82.75,62.4 ; P501.2 83.83,61.32 ; P501.2 84.91,62.4 ; 69.1,63.86 P503.1 ; P503.1 68.02,64.94 ; P503.1 70.18,64.94 ; P503.1 69.1,66.02 ; J401.5 109.26,58.03 ; J401.5 107.99,59.3 ; J401.5 106.72,58.03 ; 99.8,16.24 P706.2 100.88,15.16 ; v1(62.62,32.75) 62.62,31.53 C652.2 62.56,31.54 v1(60.79,31.54) ; v1(57.92,32.75) 57.92,31.92 57.51,31.51 C611.2 v1(55.08,31.51)
  BOTTOM w1.27: P704.2 64.75,25.07 C639.2
  vias: v1(0.27,72.88) v1(0.28,69.37) v1(0.27,49) v1(0.28,45.5) v1(0.27,25.13) v1(0.28,21.62) v1(0.32,60.94) v1(0.32,57.43) v1(0.32,37.07) v1(0.32,33.56) v1(1.04,72.1) v1(1.04,70.14) v1(1.08,60.17) v1(1.08,58.2) v1(1.04,48.23) v1(1.04,46.26) v1(1.08,36.29) v1(1.08,34.32) v1(1.04,24.35) v1(1.04,22.39) v1(2.48,46.26) v1(2.62,48.2) v1(2.87,60.18) v1(2.79,36.3) v1(2.92,58.21) v1(3.18,34.32) v1(4.29,46.29) v1(4.61,59.95) v1(4.7,36.3) v1(4.8,57.93) v1(5.08,34.32) v1(5.16,48.2) v1(6.45,59.42) v1(6.58,57.27) v1(6.6,36.3) v1(6.83,46.29) v1(6.98,34.33) v1(7.6,65.13) v1(7.61,63.76) v1(7.6,53.19) v1(7.61,51.82) v1(7.6,41.25) v1(7.61,39.88) v1(7.6,29.32) v1(7.61,27.94) v1(7.7,48.2) v1(8.05,62.62) v1(8.16,58.59) v1(8.19,56.24) v1(8.37,30.55) v1(8.41,36.88) v1(8.82,34.84) v1(9.16,65.17) v1(9.16,53.23) v1(9.18,49.36) v1(9.16,41.29) v1(9.16,29.36) v1(9.19,63.75) v1(9.19,51.81) v1(9.19,39.87) v1(9.19,27.93) v1(9.57,54.93) v1(9.59,38.38) v1(9.7,57.48) v1(9.82,41.93) v1(10,64.45) v1(10,52.51) v1(10.04,45.68) v1(10.06,44.2) v1(10,40.58) v1(10,28.64) v1(10.36,35.96) v1(10.43,60.76) v1(10.43,32.8) v1(10.59,66.96) v1(10.59,26.59) v1(11.4,37.56) v1(11.65,52.06) v1(11.63,50.62) v1(12.05,41.6) v1(12.05,40.16) v1(12.49,58.51) v1(12.49,35.04) v1(12.65,64.72) v1(12.61,50.03) v1(12.61,48.7) v1(12.65,28.83) v1(13.03,51.74) v1(13.07,45.68) v1(13.09,44.22) v1(13.44,40.15) v1(13.53,50.08) v1(14.55,56.26) v1(14.55,37.29) v1(14.71,62.47) v1(14.71,31.08) v1(15.93,74.19) v1(15.89,72.63) v1(15.96,44.89) v1(15.89,21.86) v1(15.93,20.3) v1(16.27,49.31) v1(16.61,71.79) v1(16.65,57.58) v1(16.6,54.01) v1(16.6,39.54) v1(16.61,22.7) v1(16.77,60.22) v1(16.77,33.33) v1(16.69,24.34) v1(17.15,43.83) v1(17.31,74.18) v1(17.32,72.6) v1(17.32,21.89) v1(17.31,20.31) v1(17.73,38.65) v1(17.96,71.25) v1(18.38,45.63) v1(18.36,37.32) v1(18.33,26.92) v1(18.4,44.26) v1(18.83,57.98) v1(18.83,35.58) v1(19.12,68.44) v1(19.58,56.74) v1(19.57,20.83) v1(19.97,29.49) v1(20.08,39.26) v1(20.13,81.51) v1(20.12,12.97) v1(20.29,65.62) v1(20.46,34.15) v1(20.66,44.89) v1(20.9,80.75) v1(20.89,55.73) v1(20.89,37.82) v1(20.9,13.74) v1(20.99,78.5) v1(21.21,23.4) v1(21.32,49.93) v1(21.41,74.22) v1(21.46,62.81) v1(21.64,76.05) v1(21.66,33.32) v1(21.6,32.06) v1(22.33,24.62) v1(22.57,71.4) v1(22.62,59.99) v1(22.74,73.76) v1(22.87,80.75) v1(22.86,79.44) v1(22.85,44.3) v1(22.81,33.89) v1(22.84,25.93) v1(22.86,13.74) v1(23.11,77.72) v1(23.21,49.27) v1(23.25,47.79) v1(23.24,34.63) v1(23.3,27.7) v1(23.64,81.51) v1(23.63,12.98) v1(23.74,68.58) v1(23.82,71.46) v1(23.79,57.17) v1(24.07,75.37) v1(24.27,59.32) v1(24.4,34.04) v1(24.46,28.53) v1(24.8,69.12) v1(24.88,37.2) v1(24.9,65.77) v1(25.19,73.09) v1(26.07,62.95) v1(26.17,65.16) v1(26.15,31.1) v1(26.21,70.76) v1(26.68,29.57) v1(26.69,73.1) v1(26.75,19.96) v1(27.01,70.55) v1(27.01,23) v1(27.13,68.39) v1(27.28,67.52) v1(27.24,60.14) v1(27.28,24.18) v1(27.73,33.63) v1(27.95,72.63) v1(27.99,74.19) v1(28.05,65.87) v1(28.03,25.39) v1(28.4,57.32) v1(28.67,71.79) v1(28.76,63.94) v1(28.82,28.59) v1(29.37,74.18) v1(29.38,72.6) v1(29.38,36.23) v1(29.55,61.04) v1(29.75,21.86) v1(29.79,20.3) v1(29.89,63.27) v1(29.92,57.81) v1(29.96,34.33) v1(29.96,30.26) v1(30.46,22.7) v1(30.57,66.85) v1(30.59,26.69) v1(31.19,38.55) v1(31.17,21.89) v1(31.16,20.31) v1(31.19,72.34) v1(31.28,63.25) v1(31.24,39.7) v1(31.2,34.33) v1(31.2,30.26) v1(31.31,57.79) v1(31.46,69.3) v1(31.45,60.63) v1(31.45,59.22) v1(31.46,24.25) v1(32.04,61.82) v1(32.07,57.3) v1(32.14,65.2) v1(32.14,64.18) v1(32.12,63.25) v1(32.19,81.47) v1(32.58,60.94) v1(32.53,36.2) v1(32.75,33.04) v1(32.96,80.71) v1(32.97,79.11) v1(33.08,77.21) v1(33.06,34.24) v1(33.04,30.91) v1(33.19,56.61) v1(33.16,36.88) v1(33.25,29.18) v1(33.35,75.32) v1(33.35,23.42) v1(33.63,60.94) v1(33.66,32.61) v1(33.62,21.53) v1(33.78,73.47) v1(33.97,13.02) v1(34.08,19.68) v1(34.21,71.61) v1(34.43,69.72) v1(34.46,67.83) v1(34.46,66.13) v1(34.43,64.37) v1(34.47,17.82) v1(34.71,32.61) v1(34.7,15.93) v1(34.75,13.78) v1(34.93,80.71) v1(34.92,79.51) v1(34.93,78.23) v1(34.97,60.94) v1(35.13,76.33) v1(35.25,29.18) v1(35.21,27.42) v1(35.22,25.72) v1(35.22,24.11) v1(35.38,22.72) v1(35.51,74.47) v1(35.66,21.29) v1(35.7,81.47) v1(35.97,72.62) v1(36.01,60.94) v1(36.04,32.61) v1(36.08,19.63) v1(36.27,70.74) v1(36.39,68.84) v1(36.46,67.17) v1(36.42,64.38) v1(36.46,56.56) v1(36.44,17.76) v1(36.49,36.94) v1(36.64,62.64) v1(36.64,15.86) v1(36.72,13.78) v1(37.09,59.34) v1(37.15,57.35) v1(37.09,32.61) v1(37.22,28.88) v1(37.48,13.02) v1(37.58,72.6) v1(37.56,30.31) v1(37.64,31.73) v1(37.71,69.56) v1(37.84,66.51) v1(37.97,63.47) v1(38.11,60.42) v1(38.24,57.38) v1(38.22,34.33) v1(38.43,39.7) v1(38.43,38.55) v1(38.64,19.82) v1(38.78,22.87) v1(38.91,25.91) v1(39.04,28.96) v1(39.18,32) v1(39.23,33.31) v1(39.31,35.05) v1(39.4,38.27) v1(39.63,36.14) v1(40.04,55.66) v1(40.65,36.14) v1(41.54,24.44) v1(41.7,53.46) v1(41.83,74.2) v1(41.84,42.41) v1(41.96,71.16) v1(42.1,68.11) v1(42.23,65.07) v1(42.36,62.02) v1(42.49,58.98) v1(42.63,55.93) v1(42.71,47.34) v1(43.03,21.26) v1(43.16,24.31) v1(43.32,48.86) v1(43.3,27.35) v1(43.43,30.4) v1(43.56,33.44) v1(43.62,46.4) v1(43.7,42.16) v1(43.69,36.49) v1(43.85,53.77) v1(43.83,39.54) v1(44.27,56.59) v1(44.89,62.59) v1(44.89,60.55) v1(44.89,58.52) v1(44.95,47.34) v1(45.07,64.61) v1(45.51,54.85) v1(45.64,48.84) v1(45.82,51.56) v1(45.89,66.47) v1(46.05,46.72) v1(46.57,56.3) v1(46.98,61.91) v1(46.99,58.08) v1(47.06,63.89) v1(47,60.01) v1(47.28,67.95) v1(47.4,48.86) v1(47.51,23.29) v1(47.51,22.28) v1(47.74,50.49) v1(47.76,47.42) v1(47.88,65.64) v1(48.53,24.31) v1(48.53,23.29) v1(48.53,22.28) v1(49.08,68.9) v1(49.14,66.6) v1(49.16,46.71) v1(49.32,45.02) v1(49.48,13.14) v1(49.55,24.31) v1(49.55,23.29) v1(50.05,41.32) v1(50.61,47.65) v1(51.09,69.19) v1(51.1,67.03) v1(51.26,41.08) v1(51.6,46.62) v1(51.6,42.82) v1(51.66,38.2) v1(52.32,39.52) v1(53.12,69.25) v1(53.37,48.63) v1(53.75,45.21) v1(53.88,16.47) v1(53.88,14.84) v1(54.32,46.62) v1(54.49,15.67) v1(54.83,42.15) v1(55.06,38.29) v1(55,36.77) v1(55.15,69.38) v1(55.1,16.49) v1(55.1,14.84) v1(55.39,39.17) v1(55.54,48.68) v1(55.53,45.07) v1(56.79,46.81) v1(56.9,41.24) v1(57.17,69.59) v1(57.46,48.68) v1(58.07,44.94) v1(58.1,43.17) v1(58.31,38.22) v1(58.44,35.97) v1(59.18,69.87) v1(59.13,41.58) v1(59.2,67.71) v1(59.33,46.81) v1(60,48.68) v1(60,44.94) v1(60.21,61.78) v1(60.44,39.33) v1(60.62,43.07) v1(61.18,70.22) v1(61.2,68.06) v1(61.58,35.59) v1(61.6,37.46) v1(61.87,46.81) v1(62.54,48.68) v1(62.54,44.94) v1(62.54,41.2) v1(62.92,61.51) v1(62.98,39.33) v1(63.17,70.65) v1(63.19,68.48) v1(63.16,43.07) v1(64.14,37.46) v1(64.12,35.59) v1(64.41,46.81) v1(65.08,48.68) v1(65.08,44.94) v1(65.08,41.2) v1(65.14,71.14) v1(65.16,68.98) v1(65.29,61.51) v1(65.52,39.33) v1(65.7,43.07) v1(66.68,37.46) v1(66.66,35.59) v1(66.95,46.81) v1(67.09,71.7) v1(67.11,69.54) v1(67.62,48.68) v1(67.62,44.94) v1(67.62,41.2) v1(67.83,61.51) v1(68.06,39.33) v1(68.24,43.07) v1(69.06,72.21) v1(69.08,70.04) v1(69.22,37.46) v1(69.2,35.59) v1(69.49,46.81) v1(70.16,44.94) v1(70.16,41.2) v1(70.24,61.13) v1(70.6,39.33) v1(70.78,43.07) v1(70.8,48.7) v1(71.05,72.64) v1(71.06,70.48) v1(71.41,24.12) v1(71.76,37.46) v1(71.74,35.59) v1(72.03,46.81) v1(72.7,44.94) v1(72.7,41.2) v1(72.97,48.69) v1(73.05,72.99) v1(73.06,70.83) v1(73.14,39.33) v1(73.19,24.12) v1(73.32,43.07) v1(74.05,58.89) v1(74.28,35.59) v1(74.3,37.46) v1(74.46,24.12) v1(74.57,46.81) v1(75.06,73.27) v1(75.08,71.11) v1(75.24,48.68) v1(75.24,44.94) v1(75.24,41.2) v1(75.68,39.33) v1(75.86,43.07) v1(76.11,24.12) v1(76.59,58.89) v1(76.84,37.46) v1(76.82,35.59) v1(77.08,73.47) v1(77.1,71.31) v1(77.11,46.81) v1(77.38,24.12) v1(77.78,48.68) v1(77.78,44.94) v1(77.78,41.2) v1(78.22,39.33) v1(78.4,43.07) v1(79.11,73.59) v1(79.13,71.43) v1(79.38,37.46) v1(79.36,35.59) v1(79.65,46.81) v1(79.87,61.53) v1(80.04,56.81) v1(80.32,48.68) v1(80.32,44.94) v1(80.32,41.2) v1(80.76,39.33) v1(80.94,43.07) v1(81.14,73.63) v1(81.16,71.47) v1(81.8,34.43) v1(81.83,33.69) v1(81.92,37.46) v1(81.9,35.59) v1(82.19,46.81) v1(82.86,48.68) v1(82.86,44.94) v1(82.86,41.2) v1(83.3,39.33) v1(83.48,43.07) v1(84.46,37.46) v1(84.44,35.59) v1(84.59,16.24) v1(84.73,46.81) v1(85.31,16.24) v1(85.4,48.68) v1(85.4,44.94) v1(85.4,41.2) v1(85.46,28.41) v1(85.46,27.14) v1(85.46,24.6) v1(85.46,23.33) v1(85.84,39.33) v1(86.02,43.07) v1(86.73,28.41) v1(86.73,27.14) v1(86.73,25.87) v1(86.73,24.6) v1(86.73,23.33) v1(86.82,76.17) v1(86.82,74.9) v1(86.82,73.63) v1(86.82,72.36) v1(86.82,71.09) v1(86.98,35.59) v1(87,37.46) v1(87.27,46.81) v1(87.94,48.68) v1(87.94,44.94) v1(87.94,41.2) v1(88,28.41) v1(88,27.14) v1(88,25.87) v1(88,24.6) v1(88,23.33) v1(88.09,76.17) v1(88.09,74.9) v1(88.09,73.63) v1(88.09,72.36) v1(88.38,39.33) v1(88.56,43.07) v1(89.27,28.41) v1(89.27,27.14) v1(89.27,25.87) v1(89.27,24.6) v1(89.27,23.33) v1(89.36,76.17) v1(89.36,74.9) v1(89.36,73.63) v1(89.36,72.36) v1(89.54,37.46) v1(89.52,35.59) v1(89.81,46.81) v1(90.48,48.68) v1(90.48,44.94) v1(90.48,41.2) v1(90.43,24.68) v1(90.54,28.41) v1(90.54,27.14) v1(90.54,25.87) v1(90.54,23.33) v1(90.63,76.17) v1(90.63,74.9) v1(90.63,73.63) v1(90.63,72.36) v1(90.63,71.09) v1(90.92,39.33) v1(91.1,43.07) v1(91.9,76.17) v1(91.9,74.9) v1(91.9,73.63) v1(91.9,72.36) v1(92.08,37.46) v1(92.06,35.59) v1(92.35,46.81) v1(93.02,44.94) v1(93.02,41.2) v1(93.48,48.69) v1(93.46,39.33) v1(93.64,43.07) v1(94.62,37.46) v1(94.6,35.59) v1(94.89,46.81) v1(95.56,44.94) v1(95.56,41.2) v1(95.64,48.66) v1(96,39.33) v1(96.18,43.07) v1(97.16,37.46) v1(97.14,35.59) v1(97.43,46.81) v1(98.1,44.94) v1(98.1,41.2) v1(98.32,48.69) v1(98.54,39.33) v1(99.02,35.59) v1(99.7,37.46) v1(99.97,43.07) v1(99.97,39.33) v1(100.19,46.82) v1(100.64,44.94) v1(100.64,41.2) v1(100.86,48.69) v1(101.56,35.59) v1(102.24,37.46) v1(102.51,43.07) v1(102.51,39.33) v1(102.73,46.82) v1(102.91,25.26) v1(103.18,44.94) v1(103.18,41.2) v1(103.4,48.69) v1(103.67,25.26) v1(104.1,35.59) v1(104.43,25.26) v1(104.78,37.46) v1(105.05,43.07) v1(105.05,39.33) v1(105.27,46.82) v1(105.19,25.26) v1(105.72,44.94) v1(105.72,41.2) v1(105.94,48.69) v1(105.96,25.26) v1(106.72,25.26) v1(106.94,35.61) v1(107.07,37.51) v1(107.2,46.78) v1(107.45,43.1) v1(107.48,25.26) v1(107.71,39.29) v1(107.96,45) v1(107.96,41.19) v1(108.24,25.26) v1(109.08,35.59) v1(109,25.26) v1(109.09,37.46) v1(109.37,46.81) v1(110.04,48.68) v1(110.04,44.94) v1(110.04,43.07) v1(110.04,41.2) v1(110.04,39.33) v1(111.63,37.46) v1(111.62,35.59) v1(112.53,46.74) v1(112.57,42.92) v1(112.57,39.14) v1(112.89,44.76) v1(113.3,40.92) v1(113.93,35.86) v1(114.19,48.75) v1(114.26,37.42) v1(114.37,41.58) v1(114.47,45.37) v1(115.39,44.31) v1(115.77,40.33) v1(116.28,41.89) v1(116.64,38) v1(116.98,47.61) v1(117,39.88) v1(117.23,36.37) v1(117.41,49.83) v1(117.47,45.55) v1(117.56,68.91) v1(117.5,41.7) v1(118.04,43.98) v1(118.27,48.52) v1(118.37,35.35) v1(119.15,40.92) v1(119.4,48.78) v1(119.73,36.38) v1(119.86,46.8) v1(119.92,44.76) v1(120.1,51.48) v1(120.16,42.59) v1(121.17,37.58) v1(121.84,48.49) v1(121.94,41.6) v1(122.2,43.63) v1(122.43,36.94) v1(123.14,46.84) v1(123.38,42.92) v1(123.48,53.14) v1(123.54,51.45) v1(123.6,40.61) v1(124.04,36.05) v1(124.09,27.99) v1(124.38,44.49) v1(124.34,21.64) v1(124.41,33.96) v1(124.52,45.97) v1(124.6,68.96) v1(124.83,48.7) v1(124.95,67.46) v1(125.56,41.62) v1(126.06,33) v1(126.25,19.86) v1(126.37,44.48) v1(126.44,46.82) v1(126.63,13.13) v1(126.79,37.21) v1(127.05,42.96) v1(127.16,50.72) v1(127.19,52.97) v1(127.82,40.47) v1(127.94,45.96) v1(128.53,16.3) v1(128.68,42.14) v1(128.75,55.57) v1(129.04,44.91) v1(129.04,31.92) v1(129.26,36.39) v1(129.4,48.41) v1(129.55,49.95) v1(130.06,21.64) v1(130.13,43.15) v1(130.44,13.13) v1(130.91,41.18) v1(131.07,48.43) v1(131.07,46.15) v1(134.25,13.13) v1(138.06,19.48) v1(138.06,13.13) v1(141.87,19.48) v1(141.87,16.3) v1(141.87,13.13) v1(145.68,19.48) v1(145.68,16.3) v1(145.68,13.13) v2(135.29,70.74) v2(135.29,55.5) v2(139.1,56.77) v2(140.37,56.77) v2(140.37,51.69) v2(141.65,46.65) v2(142.86,42.8) v2(145.35,43.73) v2(145.93,58.21) v2(145.92,56.86) v2(145.92,54.32) v2(145.92,51.78) v2(145.92,49.24) v2(146.06,59.27) v2(147.87,70.73) v2(147.87,65.65) v2(147.84,60.59) v2(147.87,45.35) v2(147.87,40.25) v2(147.87,35.17) v3(18.04,48.18) v3(18.17,46.27) v3(23.5,45.13) v3(25.03,47.8) v3(25.16,46.66) v3(27.8,49.65) v3(33.03,47.67) v3(39.89,52.5) v4(1.62,70.15) v4(2.35,72.09) v4(3.18,22.41) v4(3.45,24.34) v4(3.53,70.15) v4(4.25,72.09) v4(5.08,22.41) v4(5.35,24.34) v4(5.43,70.15) v4(6.16,72.09) v4(6.98,22.45) v4(7.25,24.41) v4(7.34,70.15) v4(8.06,72.08) v4(8.87,22.7) v4(8.9,46.27) v4(9.13,24.74) v4(9.24,70.05) v4(9.96,71.89) v4(10.04,48.18) v4(10.71,23.19) v4(10.94,25.33) v4(11.08,69.55) v4(11.57,46.27) v4(11.78,71.34) v4(12.48,23.91) v4(12.64,26.19) v4(12.75,68.64) v4(13.48,70.47) v4(14.17,67.37) v4(14.14,24.85) v4(14.2,27.28) v4(14.36,48.18) v4(14.36,46.27) v4(14.98,69.3) v4(15.28,65.82) v4(15.62,28.55) v4(15.66,25.99) v4(16.11,64.02) v4(16.25,67.88) v4(16.52,48.18) v4(16.61,29.86) v4(17.23,66.24) v4(17.28,61.42) v4(17.66,31.07) v4(17.76,28.18) v4(17.95,64.72) v4(18.01,59.71) v4(18.68,63.1) v4(19.63,35) v4(19.76,30.53) v4(19.85,58.56) v4(20.23,63.42) v4(20.71,31.57) v4(20.93,15.44) v4(21,59.23) v4(21.32,17.3) v4(21.66,54.18) v4(22.24,18.97) v4(22.34,39.44) v4(22.55,53.01) v4(22.85,15.16) v4(23.15,20.49) v4(23.28,40.15) v4(23.3,17.01) v4(23.57,51.86) v4(23.53,36.27) v4(23.5,22.84) v4(23.85,21.71) v4(24.17,55.55) v4(24.09,41.19) v4(24.13,18.72) v4(24.46,26.69) v4(24.65,54.34) v4(24.68,50.85) v4(24.85,38.76) v4(25.08,42.21) v4(25.26,20.44) v4(25.31,53.07) v4(25.66,39.82) v4(25.79,26.3) v4(26.11,50.02) v4(26.15,22.13) v4(26.36,52.24) v4(26.32,43.15) v4(26.53,40.66) v4(26.96,25.73) v4(27.19,31.1) v4(27.39,43.76) v4(27.57,51.77) v4(27.82,41.58) v4(28.58,26.49) v4(30.62,41.07) v4(30.97,48.99) v4(31.07,50.26) v4(31.02,46.76) v4(31.05,44.8) v4(31.38,51.38) v4(31.96,52.45) v4(32.06,46.27) v4(32.93,53.51) v4(32.93,46.43) v4(33.08,48.84) v4(33.13,49.98) v4(33.56,51.05) v4(34.02,54.35) v4(34.48,52.12) v4(35.26,54.99) v4(35.39,52.73) v4(35.89,47.12) v4(36.08,49.65) v4(36.1,50.62) v4(36.36,53.18) v4(38.19,55.53) v4(40.65,36.14) v4(41.33,38.2) v4(41.82,39.19) v4(43.85,38.78) v4(43.93,38.02) v4(118.25,27.99) v4(121.8,24.3) v4(126.12,27.99) v4(126.12,24.3) v5(41.03,48.74) v5(43.44,50.34) v5(43.95,52.12) v5(47,42.59) v5(47.38,45.13) v5(50.38,49.17) v5(51.85,44.22) v5(52.84,45.26) v5(54.67,43.58) v5(119.72,38.53) v5(124.11,38.58) v5(125.21,39.57) v5(126.25,34.64) v5(127.14,38.81) v5(128.74,33.6) v5(130.39,37.99) v5(131.4,32.91) v5(133.99,37.77) v5(135.26,50.34) v5(135.26,45.26) v5(136.58,37.74) v5(136.69,39.04) v5(137.8,49.2) v5(139.07,37.77) v5(141.61,39.04) v5(144.31,44.45) v5(145.22,33.83) v5(145.3,39.14) v6(41.03,48.74) v8(10.19,43.38) v8(10.8,53.64) v8(11.07,56.15) v8(11.88,44.25) v8(11.79,39.42) v8(12.07,55.16) v8(13.06,42.31) v8(13.06,41.32) v8(14.17,53.89) v8(14.17,44.4) v8(14.8,39.99) v8(15.5,53.89) v8(15.5,44.4) v8(17.15,53.32) v8(17.15,52.28) v8(17.15,50.94) v8(17.15,49.89) v8(17.15,42.78) v8(17.15,41.45) v8(17.15,40.4) v8(18.68,39.58) v8(18.71,49.07) v8(19.41,53.93) v8(19.61,47.69) v8(20.33,50.43) v8(20.33,40.85) v8(20.84,53.55) v8(20.79,46.2) v8(21.28,44.05) v8(21.25,41.19) v8(21.41,50.69) v8(22.42,53.55) v8(22.96,50.75) v8(23.13,41.58) v8(23.41,43.86) v8(24.06,53.22) v8(24.27,50.69) v8(24.98,42.03) v8(25.03,44.51) v8(25.38,49.48) v8(25.69,52.23) v8(26.58,45.61) v8(26.62,48.08) v8(26.59,43.05) v8(26.98,50.82) v8(27.77,47.45) v8(27.7,43.83) v8(33.22,26.39) v8(33.28,24.72) v8(38.9,37.49) v8(47.96,40.53) v8(48.02,42.23) v8(128.91,52.75) v8(130.44,51.1) v8(133.99,63.29) v8(135.39,68.37) v8(135.65,63.29) v8(136.41,69.9) v8(137.04,68.25) v8(137.55,71.17) v8(137.8,48.05) v8(138.06,59.36) v8(138.69,70.15) v8(139.07,71.93) v8(140.6,43.86) v8(140.78,65.58) v8(141.11,52.88) v8(142.76,67.1) v8(144.79,40.43) v8(144.92,71.17) v8(144.92,69.52) v8(144.92,35.35) v8(146.19,40.94)
